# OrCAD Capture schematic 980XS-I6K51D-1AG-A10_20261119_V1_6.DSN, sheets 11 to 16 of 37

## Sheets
11 P0033_S3_MIPI: size A2
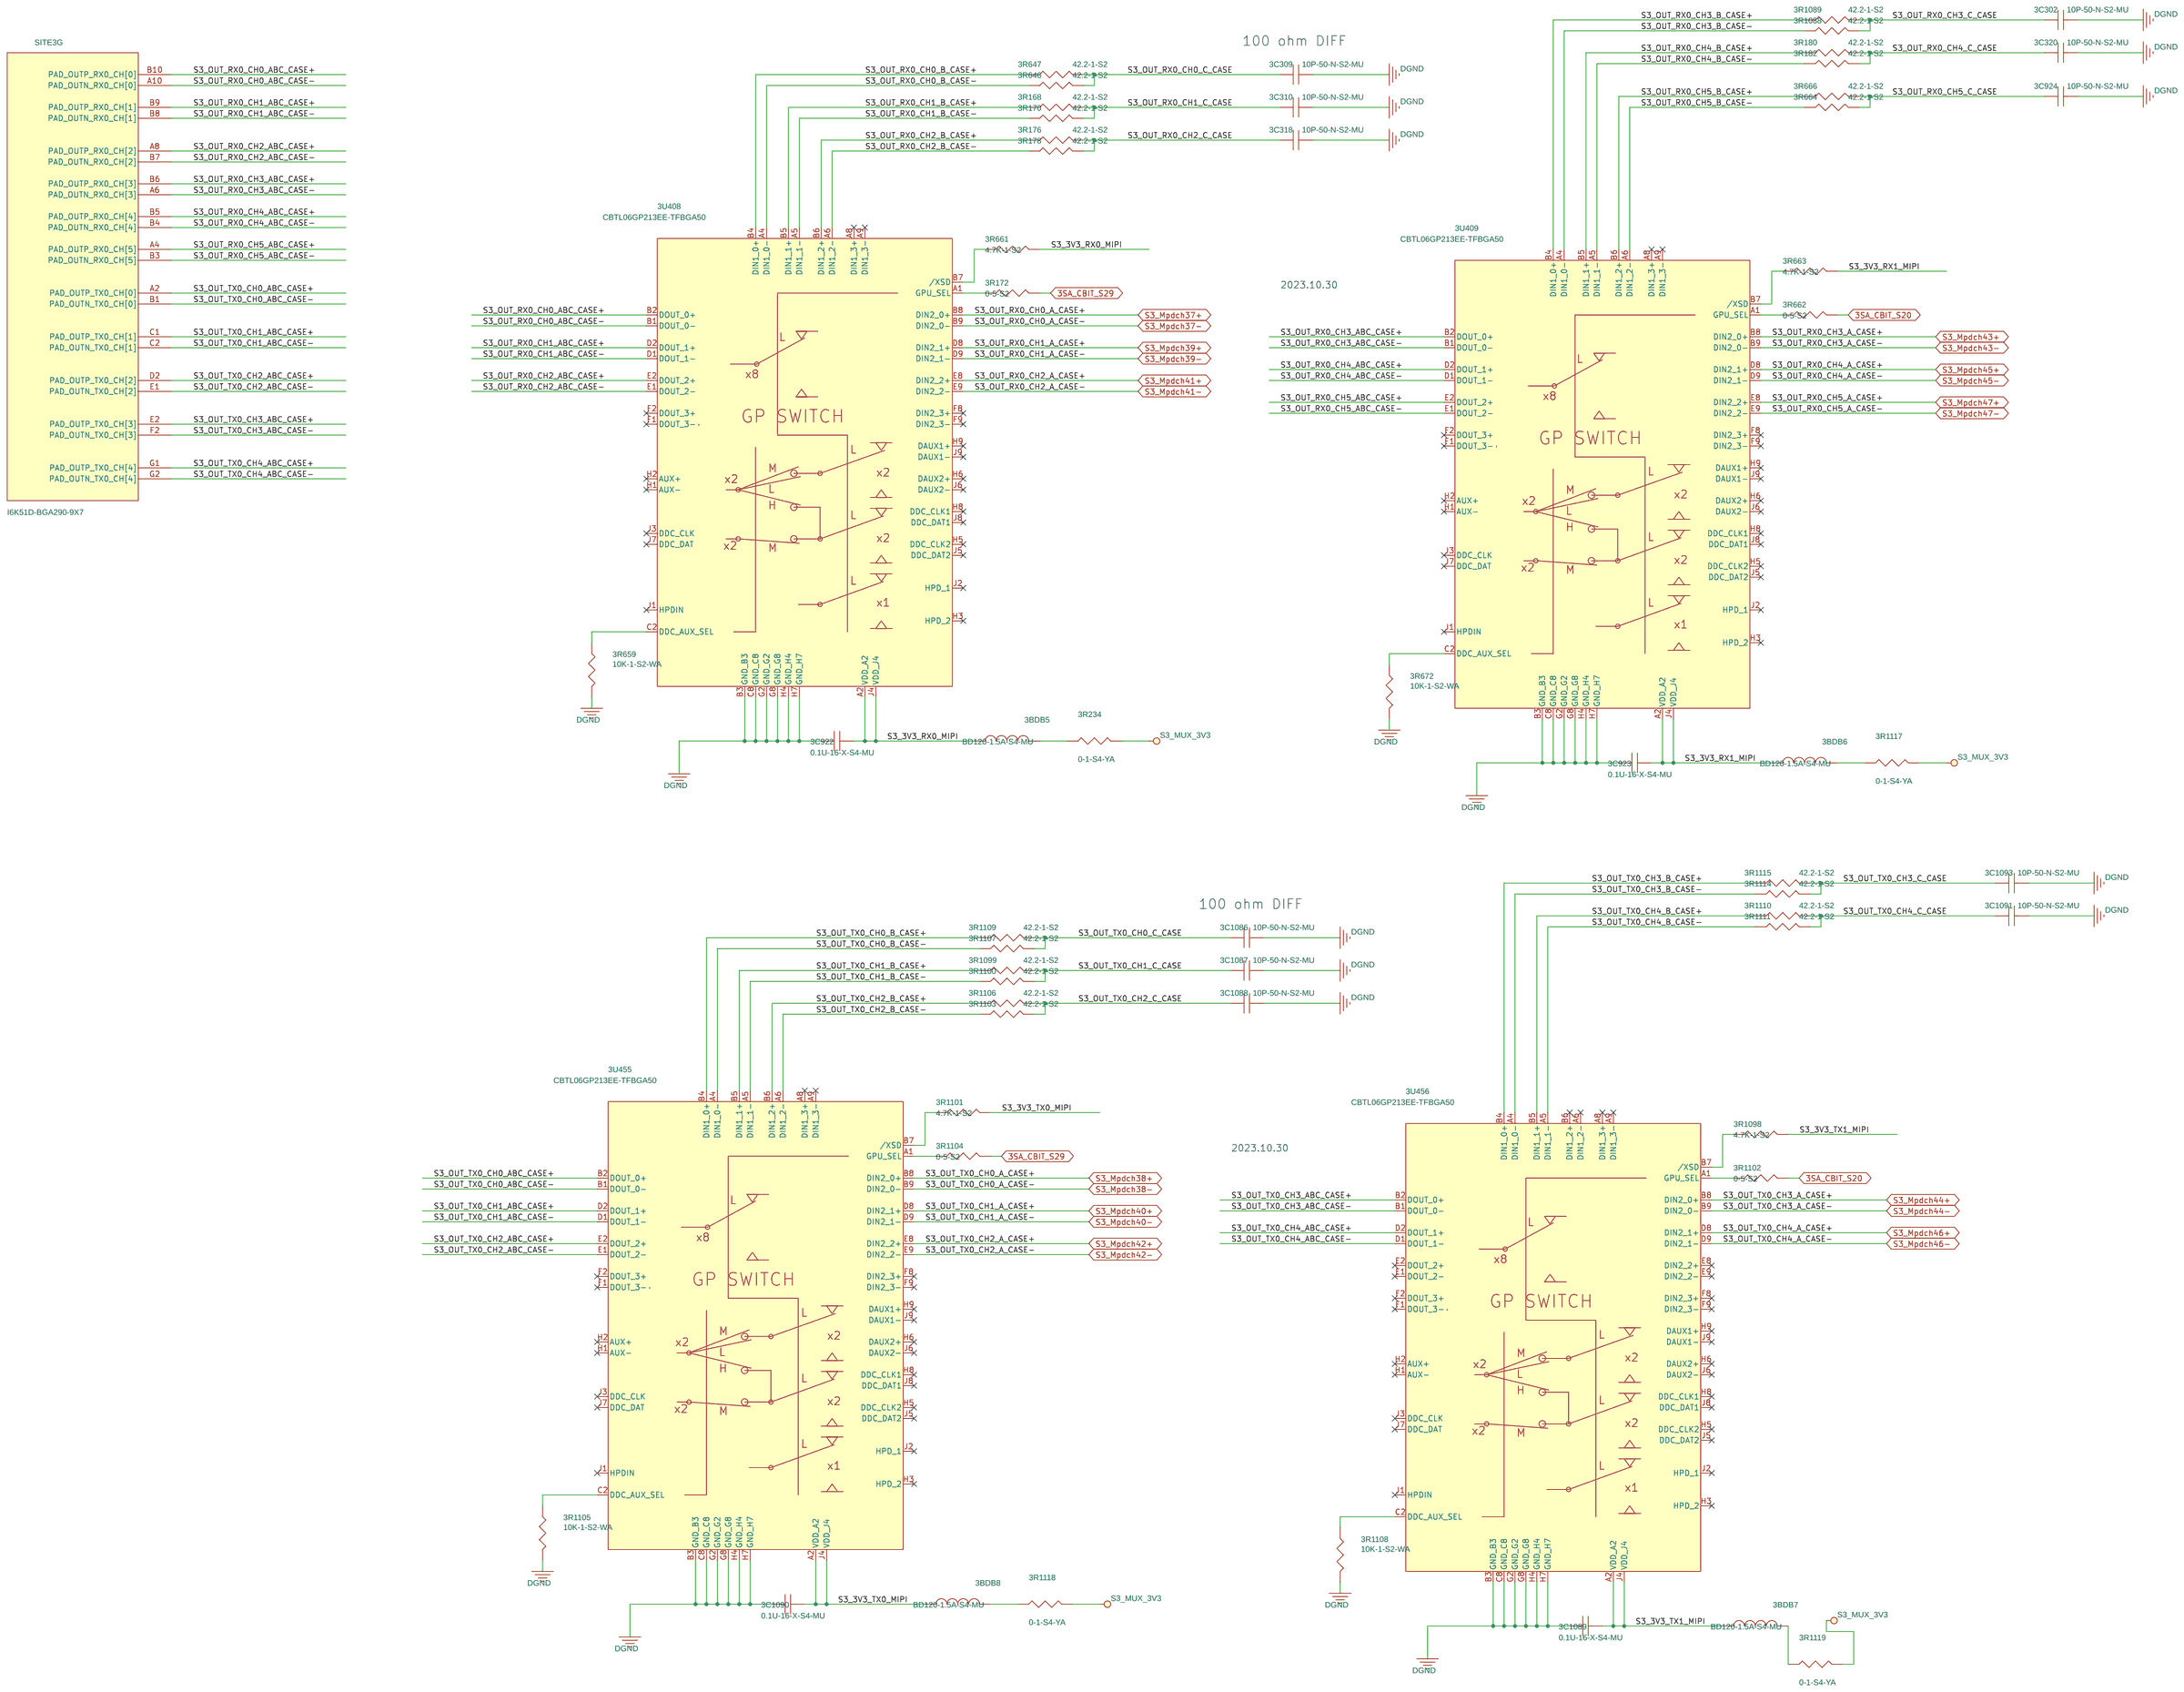
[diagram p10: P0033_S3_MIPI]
12 P0031_S3_POWER: size A2
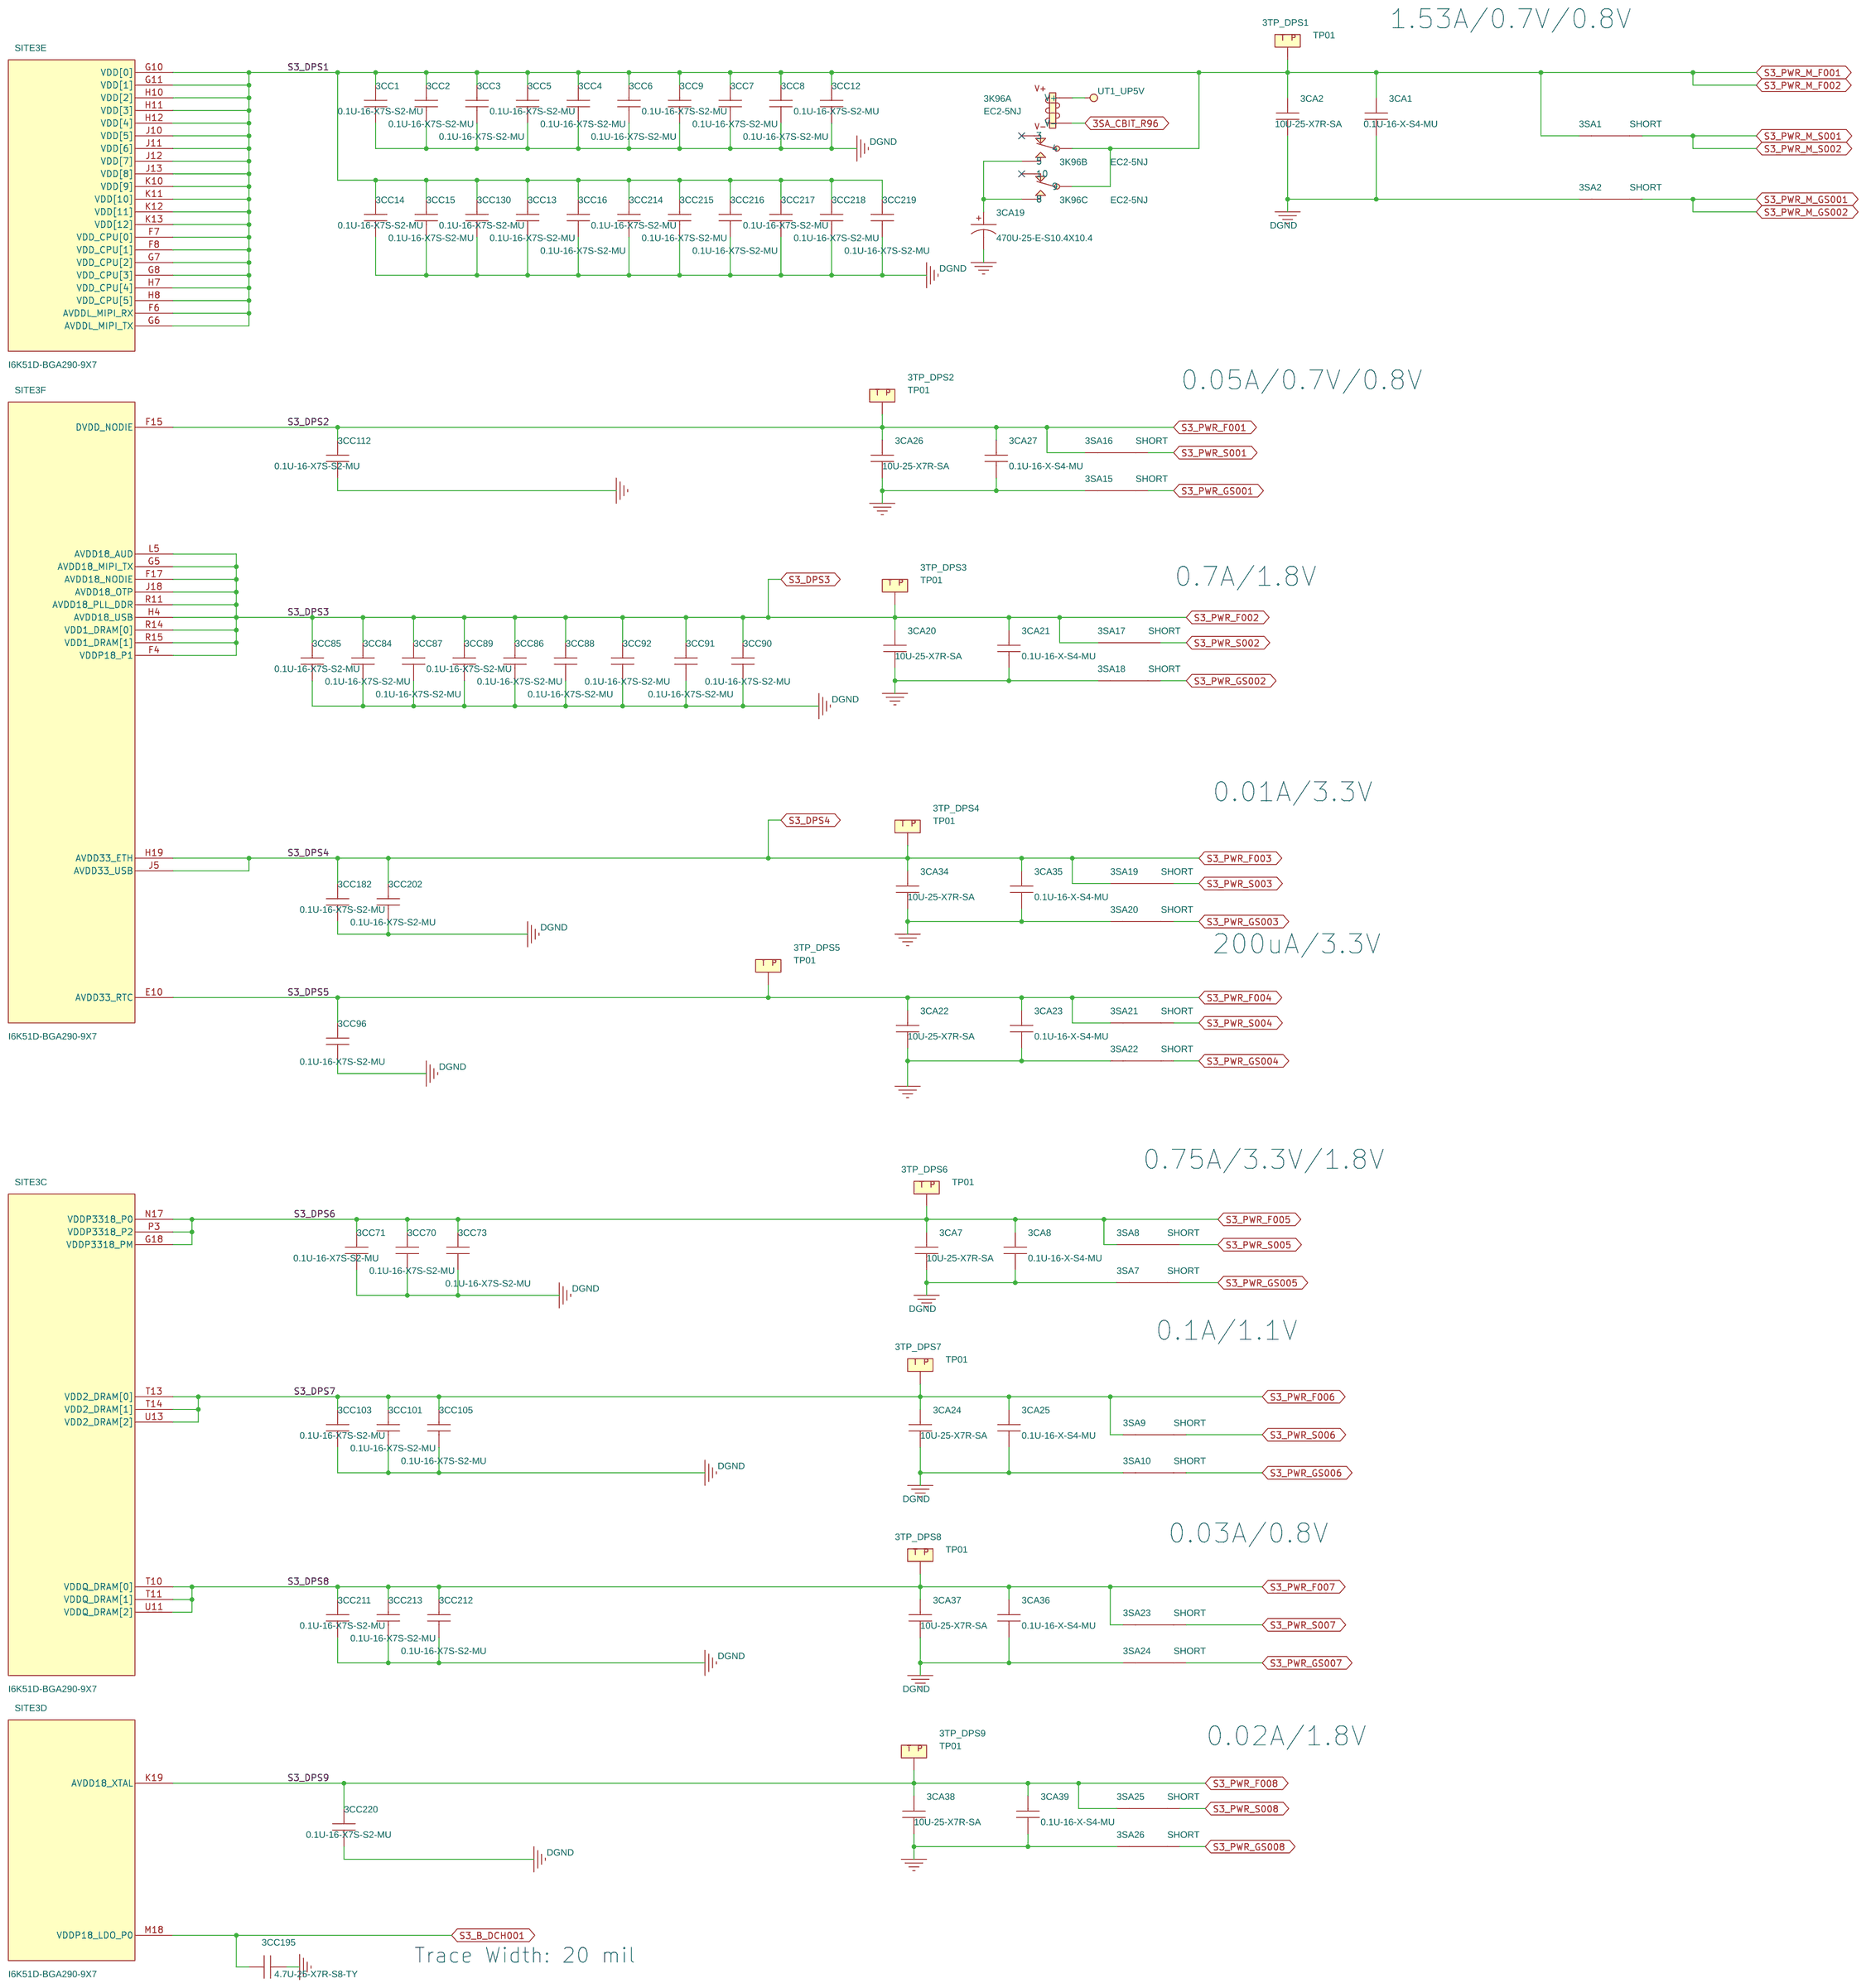
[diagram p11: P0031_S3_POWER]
13 P0023_S2_MIPI: size A2
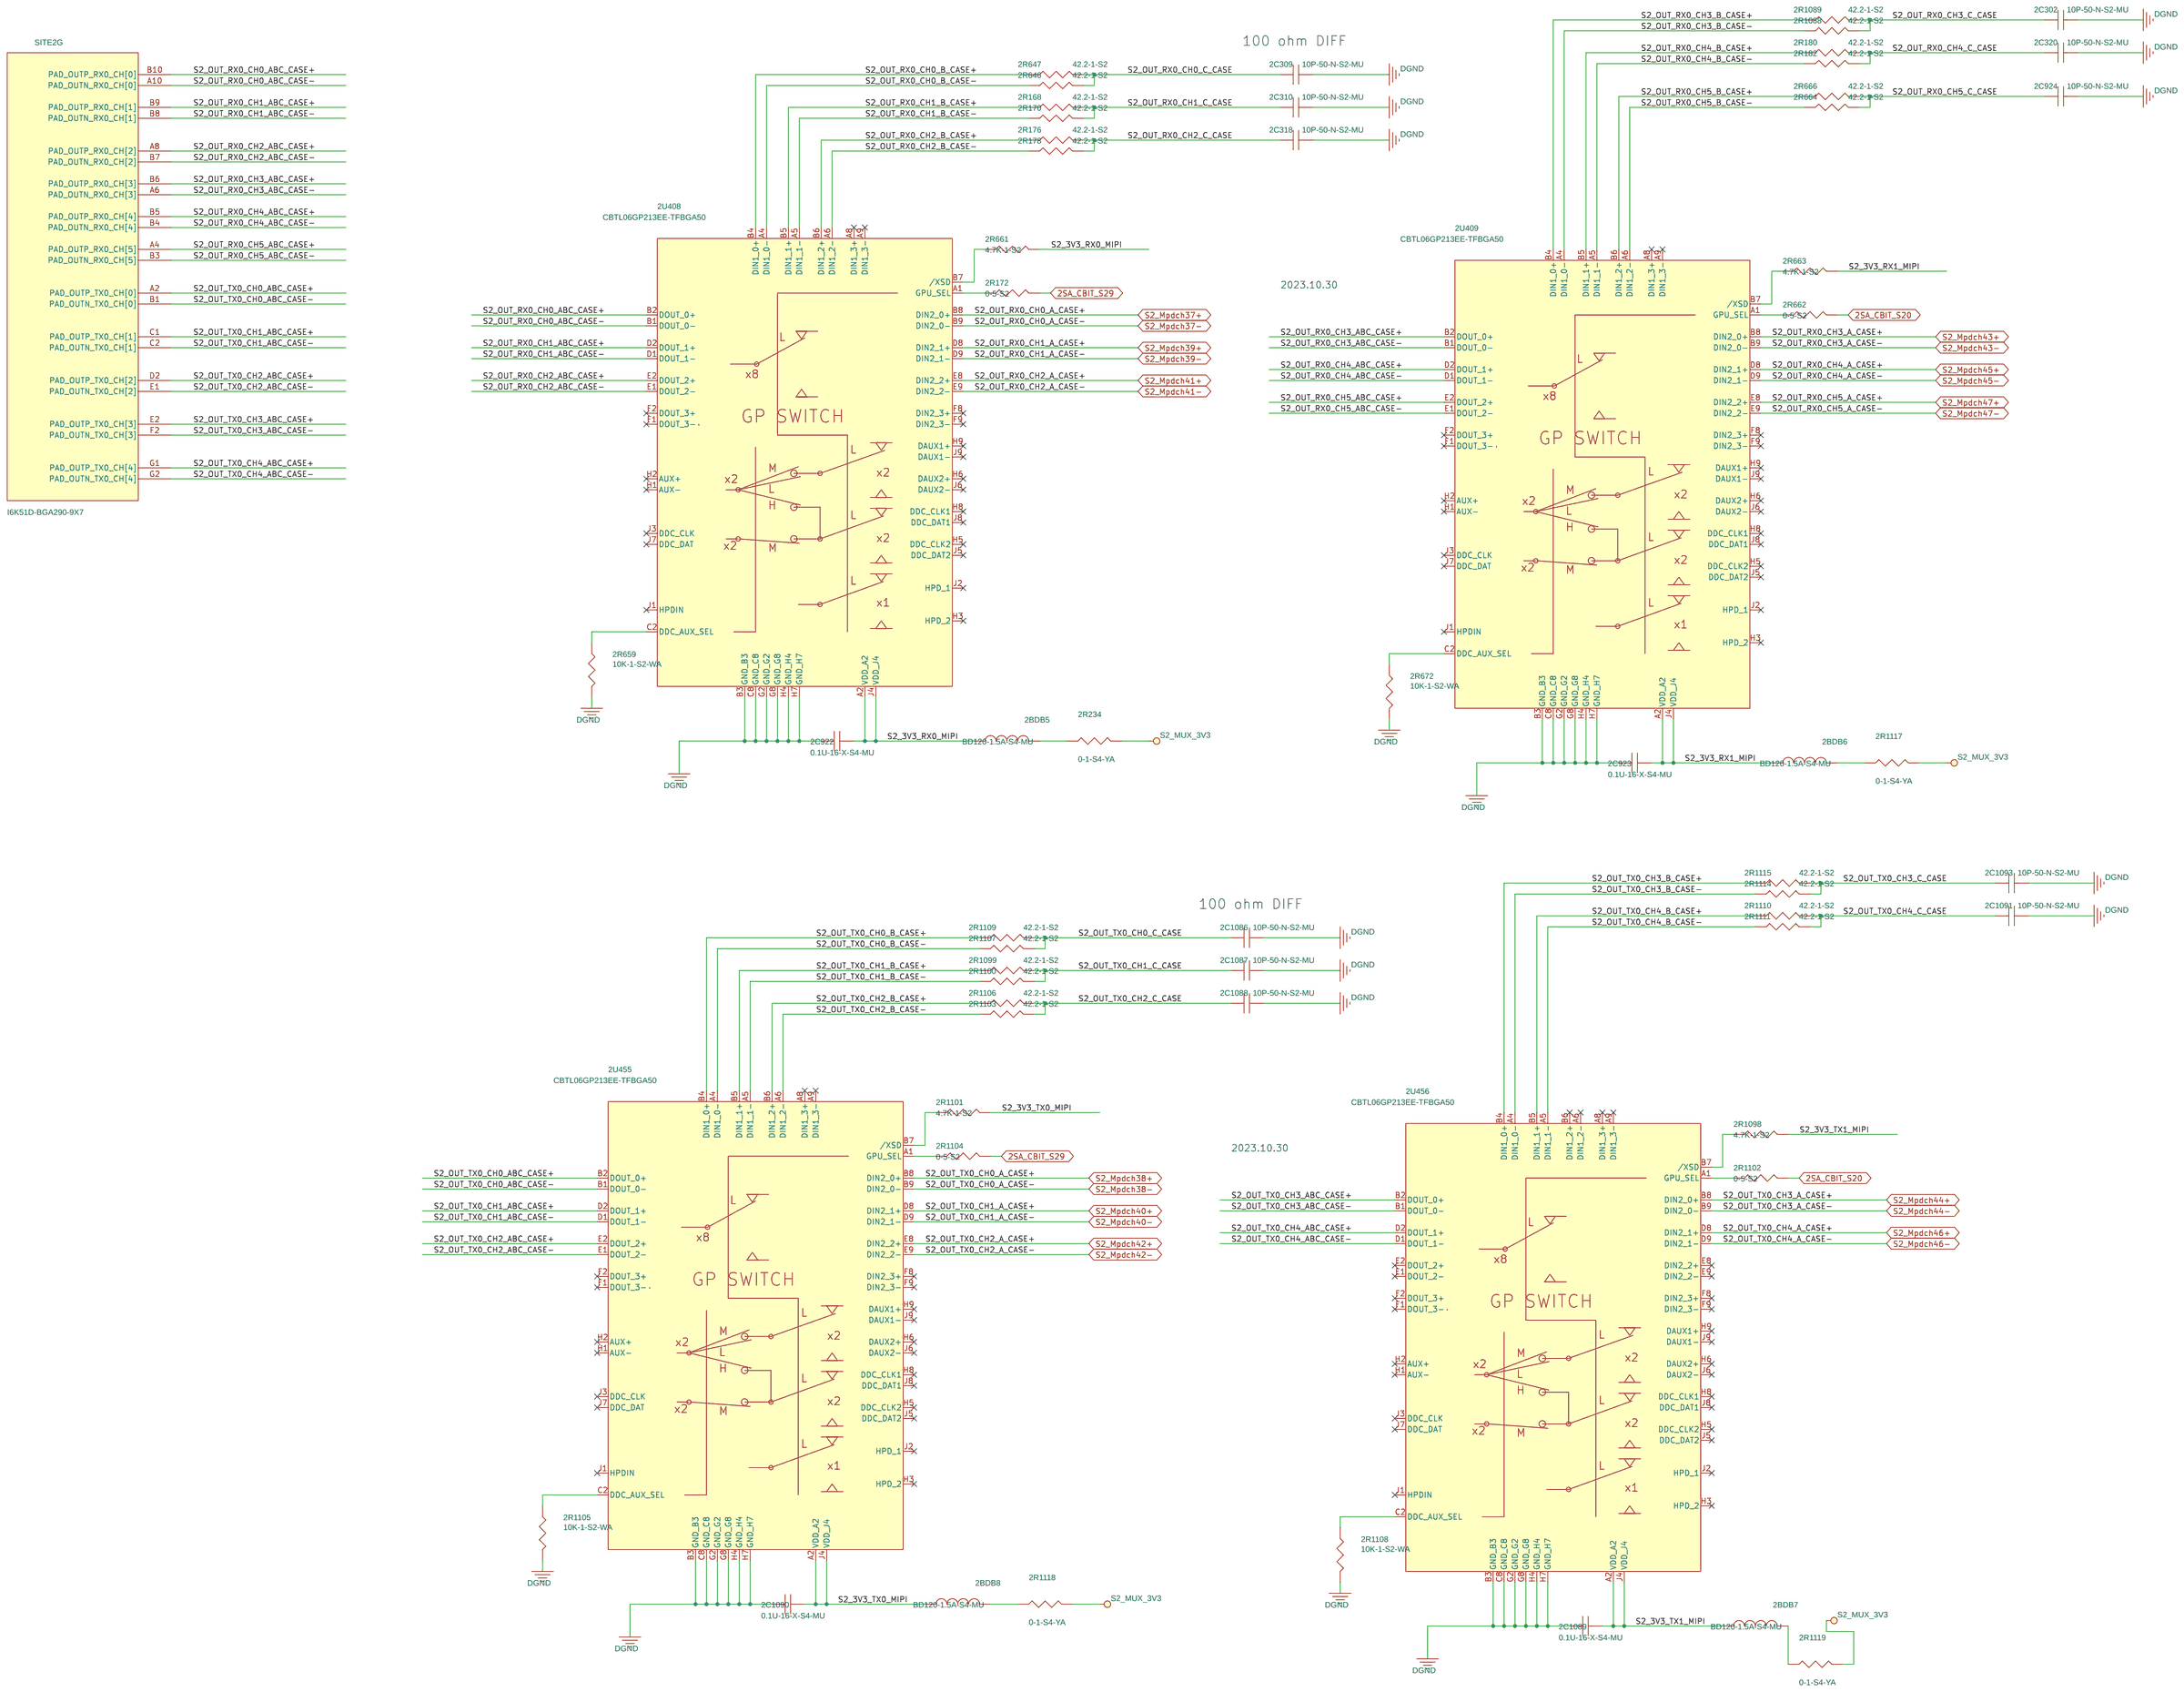
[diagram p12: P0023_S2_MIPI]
14 P0021_S2_POWER: size A2
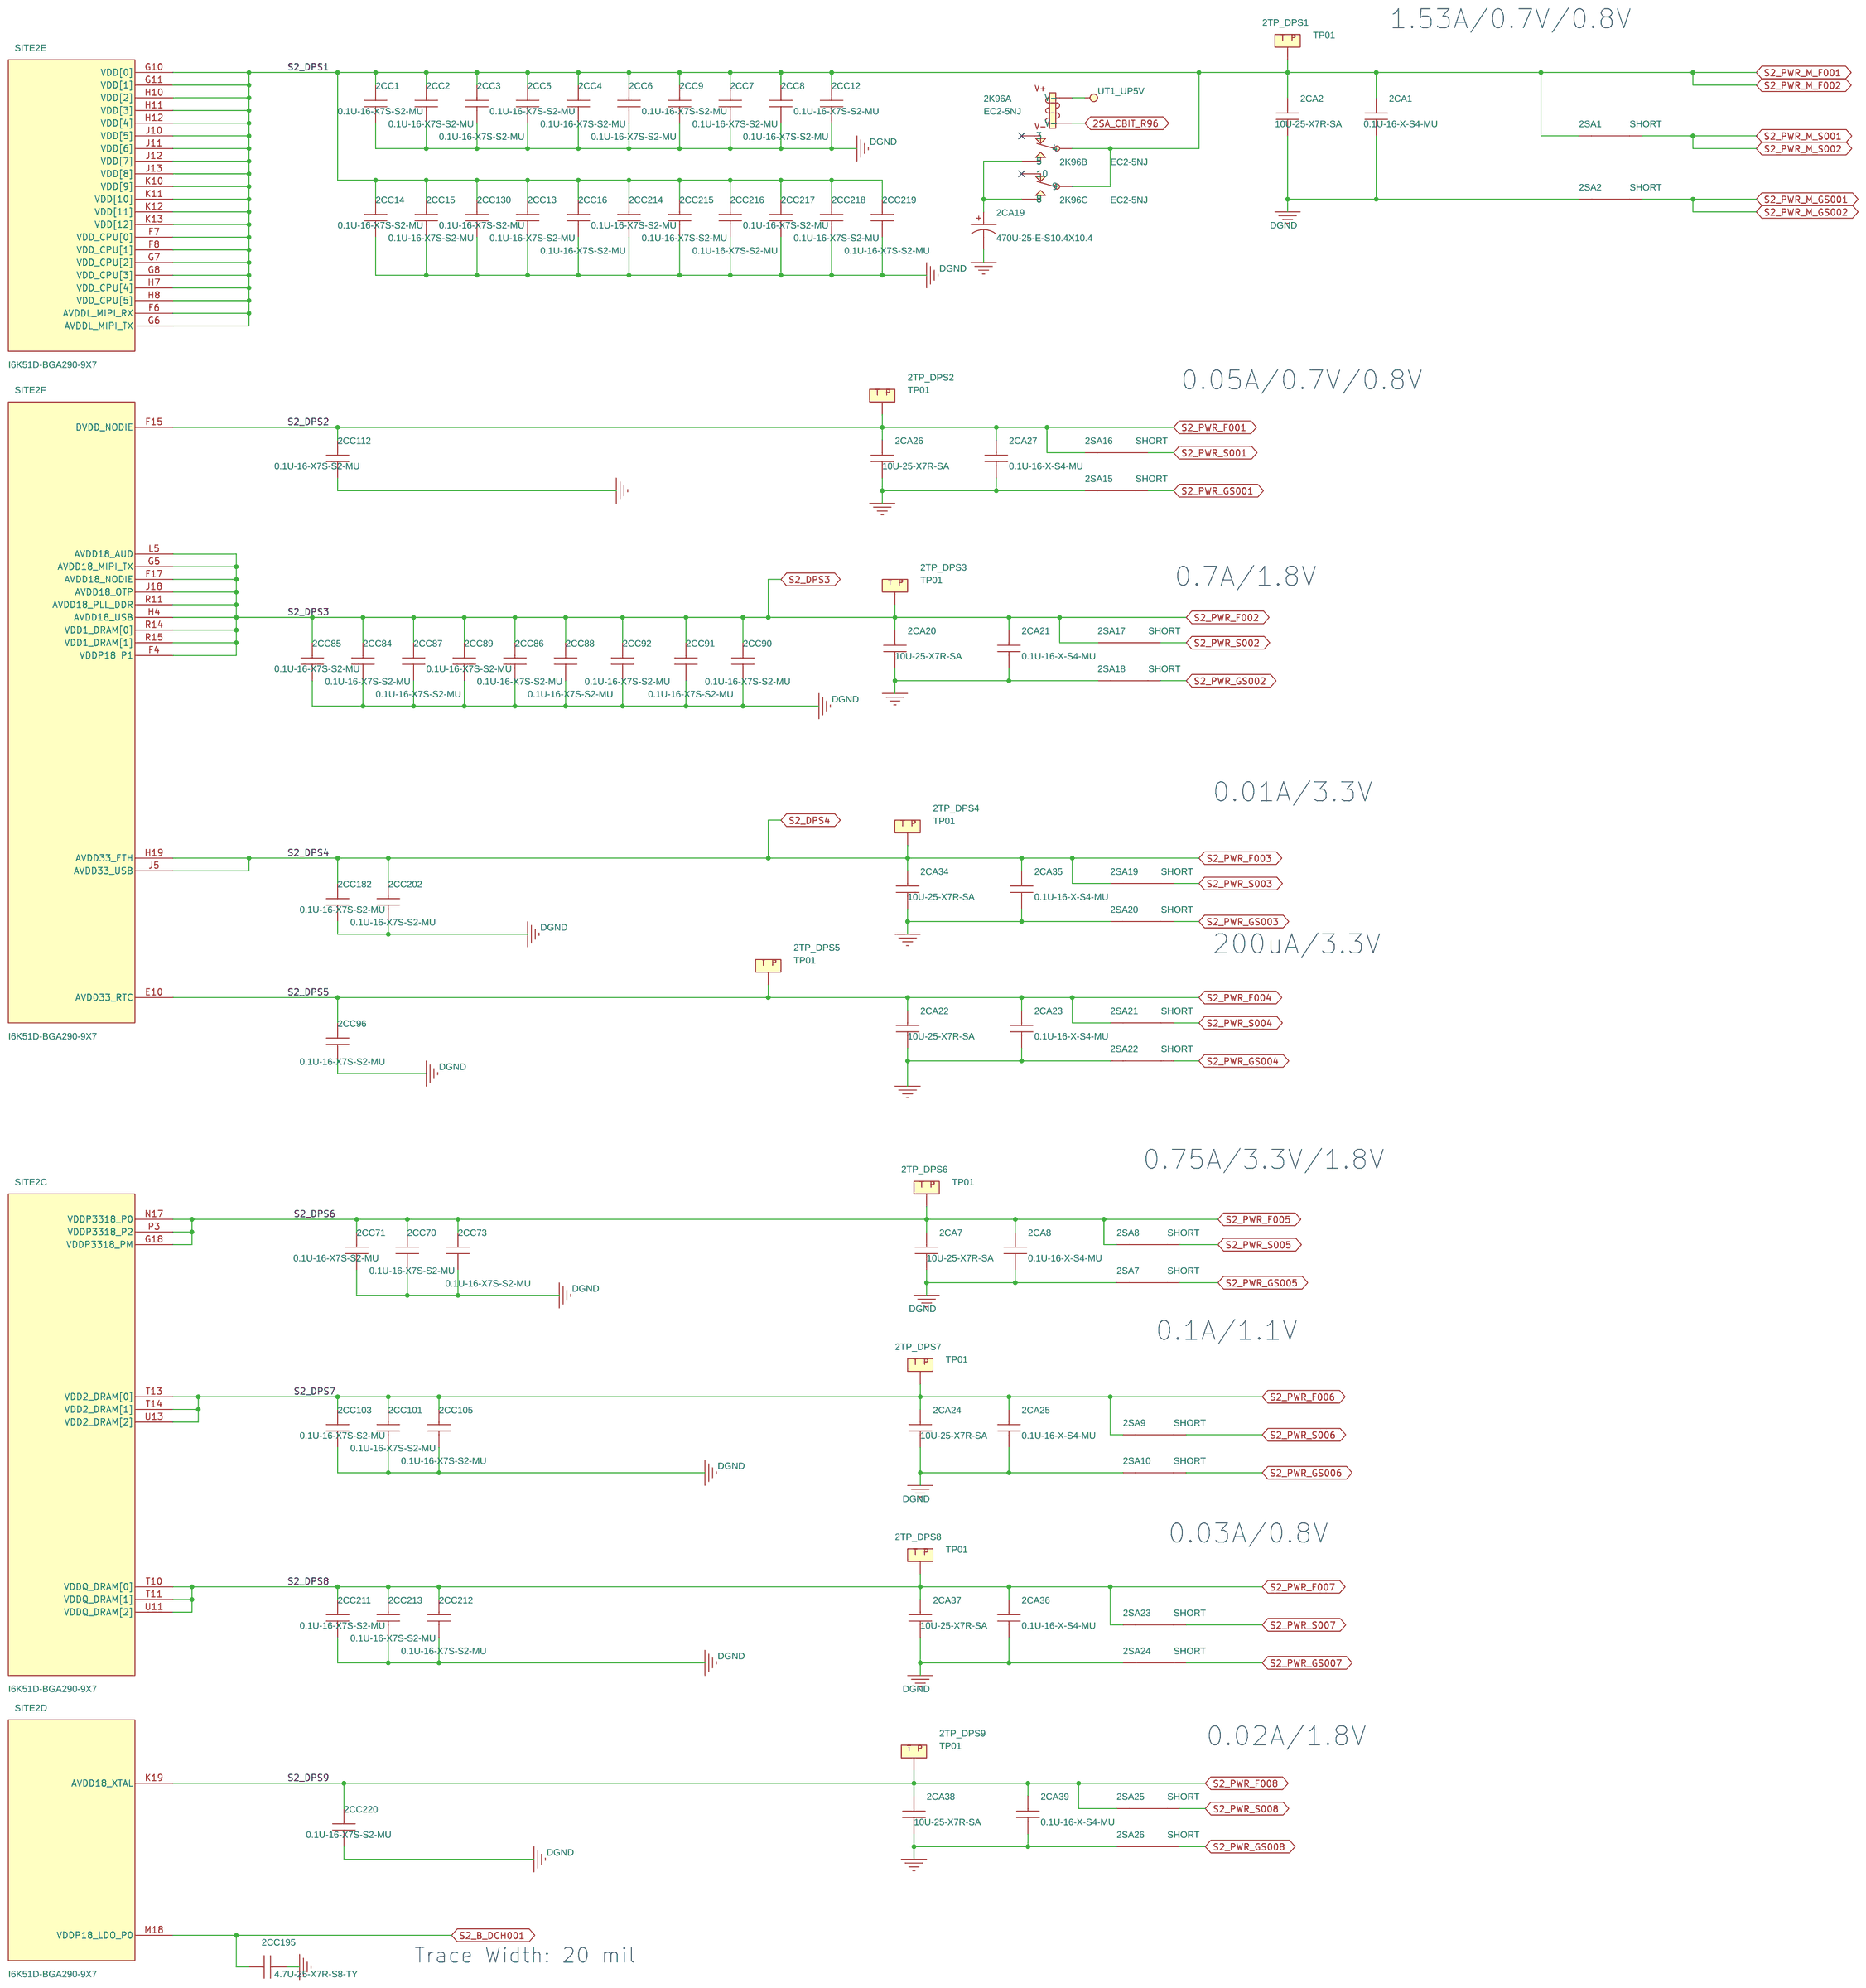
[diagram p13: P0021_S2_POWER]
15 A001-V93K_TESTConfig
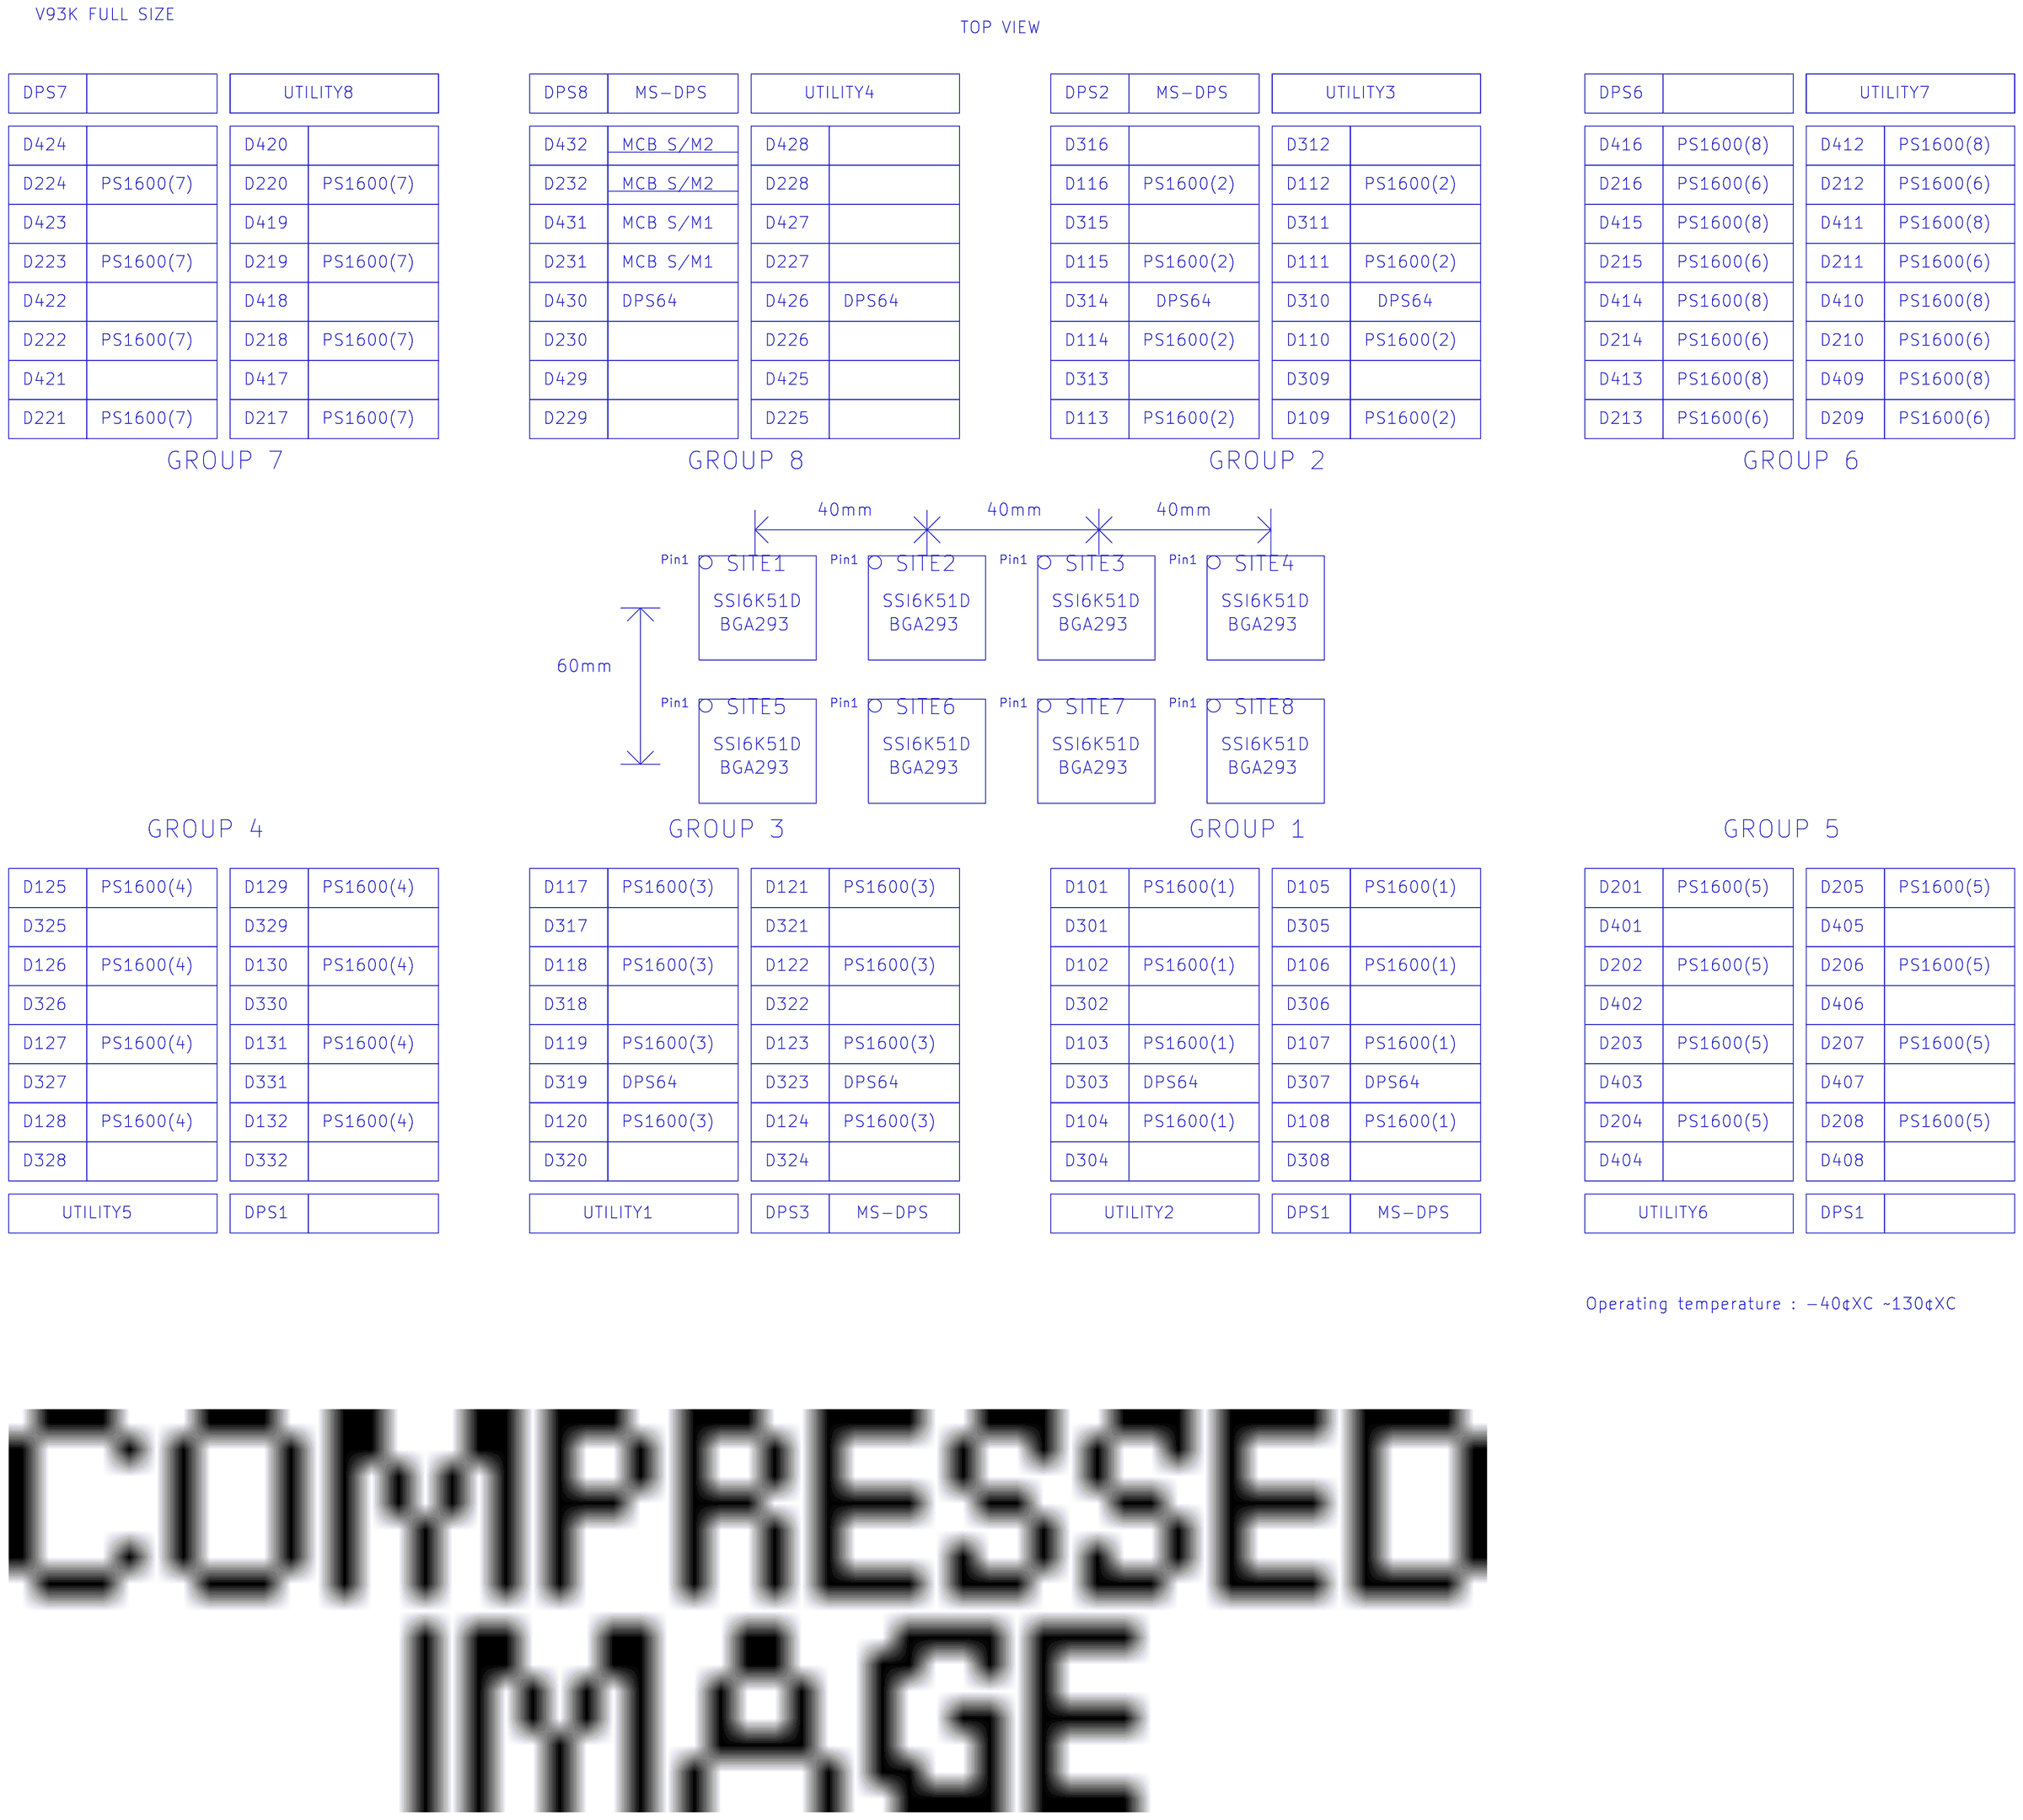
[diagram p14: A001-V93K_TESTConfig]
16 A002-History
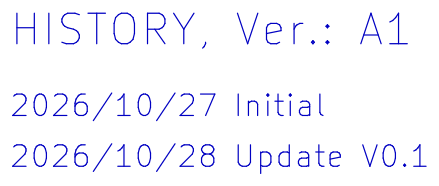
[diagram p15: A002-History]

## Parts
sheet P0021_S2_POWER
2CA1  0.1U-16-X-S4-MU  [C0402]
2CA2  10U-25-X7R-SA  [C1206]
2CA7  10U-25-X7R-SA  [C1206]
2CA8  0.1U-16-X-S4-MU  [C0402]
2CA19  470U-25-E-S10.4X10.4  [EC_10P3X10_S]
2CA20  10U-25-X7R-SA  [C1206]
2CA21  0.1U-16-X-S4-MU  [C0402]
2CA22  10U-25-X7R-SA  [C1206]
2CA23  0.1U-16-X-S4-MU  [C0402]
2CA24  10U-25-X7R-SA  [C1206]
2CA25  0.1U-16-X-S4-MU  [C0402]
2CA26  10U-25-X7R-SA  [C1206]
2CA27  0.1U-16-X-S4-MU  [C0402]
2CA34  10U-25-X7R-SA  [C1206]
2CA35  0.1U-16-X-S4-MU  [C0402]
2CA36  0.1U-16-X-S4-MU  [C0402]
2CA37  10U-25-X7R-SA  [C1206]
2CA38  10U-25-X7R-SA  [C1206]
2CA39  0.1U-16-X-S4-MU  [C0402]
2CC1  0.1U-16-X7S-S2-MU  [C0201_MINI]
2CC2  0.1U-16-X7S-S2-MU  [C0201_MINI]
2CC3  0.1U-16-X7S-S2-MU  [C0201_MINI]
2CC4  0.1U-16-X7S-S2-MU  [C0201_MINI]
2CC5  0.1U-16-X7S-S2-MU  [C0201_MINI]
2CC6  0.1U-16-X7S-S2-MU  [C0201_MINI]
2CC7  0.1U-16-X7S-S2-MU  [C0201_MINI]
2CC8  0.1U-16-X7S-S2-MU  [C0201_MINI]
2CC9  0.1U-16-X7S-S2-MU  [C0201_MINI]
2CC12  0.1U-16-X7S-S2-MU  [C0201_MINI]
2CC13  0.1U-16-X7S-S2-MU  [C0201_MINI]
2CC14  0.1U-16-X7S-S2-MU  [C0201_MINI]
2CC15  0.1U-16-X7S-S2-MU  [C0201_MINI]
2CC16  0.1U-16-X7S-S2-MU  [C0201_MINI]
2CC70  0.1U-16-X7S-S2-MU  [C0201_MINI]
2CC71  0.1U-16-X7S-S2-MU  [C0201_MINI]
2CC73  0.1U-16-X7S-S2-MU  [C0201_MINI]
2CC84  0.1U-16-X7S-S2-MU  [C0201_MINI]
2CC85  0.1U-16-X7S-S2-MU  [C0201_MINI]
2CC86  0.1U-16-X7S-S2-MU  [C0201_MINI]
2CC87  0.1U-16-X7S-S2-MU  [C0201_MINI]
2CC88  0.1U-16-X7S-S2-MU  [C0201_MINI]
2CC89  0.1U-16-X7S-S2-MU  [C0201_MINI]
2CC90  0.1U-16-X7S-S2-MU  [C0201_MINI]
2CC91  0.1U-16-X7S-S2-MU  [C0201_MINI]
2CC92  0.1U-16-X7S-S2-MU  [C0201_MINI]
2CC96  0.1U-16-X7S-S2-MU  [C0201_MINI]
2CC101  0.1U-16-X7S-S2-MU  [C0201_MINI]
2CC103  0.1U-16-X7S-S2-MU  [C0201_MINI]
2CC105  0.1U-16-X7S-S2-MU  [C0201_MINI]
2CC112  0.1U-16-X7S-S2-MU  [C0201_MINI]
2CC130  0.1U-16-X7S-S2-MU  [C0201_MINI]
2CC182  0.1U-16-X7S-S2-MU  [C0201_MINI]
2CC195  4.7U-25-X7R-S8-TY  [C0805]
2CC202  0.1U-16-X7S-S2-MU  [C0201_MINI]
2CC211  0.1U-16-X7S-S2-MU  [C0201_MINI]
2CC212  0.1U-16-X7S-S2-MU  [C0201_MINI]
2CC213  0.1U-16-X7S-S2-MU  [C0201_MINI]
2CC214  0.1U-16-X7S-S2-MU  [C0201_MINI]
2CC215  0.1U-16-X7S-S2-MU  [C0201_MINI]
2CC216  0.1U-16-X7S-S2-MU  [C0201_MINI]
2CC217  0.1U-16-X7S-S2-MU  [C0201_MINI]
2CC218  0.1U-16-X7S-S2-MU  [C0201_MINI]
2CC219  0.1U-16-X7S-S2-MU  [C0201_MINI]
2CC220  0.1U-16-X7S-S2-MU  [C0201_MINI]
2K96  EC2-5NJ  [RL_NECEC2_10P_5V]  (sections A,B,C)
2SA1  SHORT  [DEFAULT_SHORT_SMALL]
2SA2  SHORT  [DEFAULT_SHORT_SMALL]
2SA7  SHORT  [DEFAULT_SHORT_SMALL]
2SA8  SHORT  [DEFAULT_SHORT_SMALL]
2SA9  SHORT  [DEFAULT_SHORT_SMALL]
2SA10  SHORT  [DEFAULT_SHORT_SMALL]
2SA15  SHORT  [DEFAULT_SHORT_SMALL]
2SA16  SHORT  [DEFAULT_SHORT_SMALL]
2SA17  SHORT  [DEFAULT_SHORT_SMALL]
2SA18  SHORT  [DEFAULT_SHORT_SMALL]
2SA19  SHORT  [DEFAULT_SHORT_SMALL]
2SA20  SHORT  [DEFAULT_SHORT_SMALL]
2SA21  SHORT  [DEFAULT_SHORT_SMALL]
2SA22  SHORT  [DEFAULT_SHORT_SMALL]
2SA23  SHORT  [DEFAULT_SHORT_SMALL]
2SA24  SHORT  [DEFAULT_SHORT_SMALL]
2SA25  SHORT  [DEFAULT_SHORT_SMALL]
2SA26  SHORT  [DEFAULT_SHORT_SMALL]
2TP_DPS1  TP01  [TP_040_T]
2TP_DPS2  TP01  [TP_040_T]
2TP_DPS3  TP01  [TP_040_T]
2TP_DPS4  TP01  [TP_040_T]
2TP_DPS5  TP01  [TP_040_T]
2TP_DPS6  TP01  [TP_040_T]
2TP_DPS7  TP01  [TP_040_T]
2TP_DPS8  TP01  [TP_040_T]
2TP_DPS9  TP01  [TP_040_T]
SITE2  I6K51D-BGA290-9X7  [SK_TFBGA7X9_290P_0P4MM_JG]  (sections A,B,C,D,E,F,G,H,I,J,K,L,M,N,O)
sheet P0023_S2_MIPI
2BDB5  BD120-1.5A-S4-MU  [FB0402]
2BDB6  BD120-1.5A-S4-MU  [FB0402]
2BDB7  BD120-1.5A-S4-MU  [FB0402]
2BDB8  BD120-1.5A-S4-MU  [FB0402]
2C302  10P-50-N-S2-MU  [C0201]
2C309  10P-50-N-S2-MU  [C0201]
2C310  10P-50-N-S2-MU  [C0201]
2C318  10P-50-N-S2-MU  [C0201]
2C320  10P-50-N-S2-MU  [C0201]
2C922  0.1U-16-X-S4-MU  [C0402]
2C923  0.1U-16-X-S4-MU  [C0402]
2C924  10P-50-N-S2-MU  [C0201]
2C1086  10P-50-N-S2-MU  [C0201]
2C1087  10P-50-N-S2-MU  [C0201]
2C1088  10P-50-N-S2-MU  [C0201]
2C1089  0.1U-16-X-S4-MU  [C0402]
2C1090  0.1U-16-X-S4-MU  [C0402]
2C1091  10P-50-N-S2-MU  [C0201]
2C1093  10P-50-N-S2-MU  [C0201]
2R168  42.2-1-S2  [R0201]
2R170  42.2-1-S2  [R0201]
2R172  0-5-S2  [R0201]
2R176  42.2-1-S2  [R0201]
2R178  42.2-1-S2  [R0201]
2R180  42.2-1-S2  [R0201]
2R182  42.2-1-S2  [R0201]
2R234  0-1-S4-YA  [R0402]
2R646  42.2-1-S2  [R0201]
2R647  42.2-1-S2  [R0201]
2R659  10K-1-S2-WA  [R0201]
2R661  4.7K-1-S2  [R0201]
2R662  0-5-S2  [R0201]
2R663  4.7K-1-S2  [R0201]
2R664  42.2-1-S2  [R0201]
2R666  42.2-1-S2  [R0201]
2R672  10K-1-S2-WA  [R0201]
2R1088  42.2-1-S2  [R0201]
2R1089  42.2-1-S2  [R0201]
2R1098  4.7K-1-S2  [R0201]
2R1099  42.2-1-S2  [R0201]
2R1100  42.2-1-S2  [R0201]
2R1101  4.7K-1-S2  [R0201]
2R1102  0-5-S2  [R0201]
2R1103  42.2-1-S2  [R0201]
2R1104  0-5-S2  [R0201]
2R1105  10K-1-S2-WA  [R0201]
2R1106  42.2-1-S2  [R0201]
2R1107  42.2-1-S2  [R0201]
2R1108  10K-1-S2-WA  [R0201]
2R1109  42.2-1-S2  [R0201]
2R1110  42.2-1-S2  [R0201]
2R1111  42.2-1-S2  [R0201]
2R1114  42.2-1-S2  [R0201]
2R1115  42.2-1-S2  [R0201]
2R1117  0-1-S4-YA  [R0402]
2R1118  0-1-S4-YA  [R0402]
2R1119  0-1-S4-YA  [R0402]
2U408  CBTL06GP213EE-TFBGA50  [TFBGA9X9_50P_0P5MM]
2U409  CBTL06GP213EE-TFBGA50  [TFBGA9X9_50P_0P5MM]
2U455  CBTL06GP213EE-TFBGA50  [TFBGA9X9_50P_0P5MM]
2U456  CBTL06GP213EE-TFBGA50  [TFBGA9X9_50P_0P5MM]
sheet P0031_S3_POWER
3CA1  0.1U-16-X-S4-MU  [C0402]
3CA2  10U-25-X7R-SA  [C1206]
3CA7  10U-25-X7R-SA  [C1206]
3CA8  0.1U-16-X-S4-MU  [C0402]
3CA19  470U-25-E-S10.4X10.4  [EC_10P3X10_S]
3CA20  10U-25-X7R-SA  [C1206]
3CA21  0.1U-16-X-S4-MU  [C0402]
3CA22  10U-25-X7R-SA  [C1206]
3CA23  0.1U-16-X-S4-MU  [C0402]
3CA24  10U-25-X7R-SA  [C1206]
3CA25  0.1U-16-X-S4-MU  [C0402]
3CA26  10U-25-X7R-SA  [C1206]
3CA27  0.1U-16-X-S4-MU  [C0402]
3CA34  10U-25-X7R-SA  [C1206]
3CA35  0.1U-16-X-S4-MU  [C0402]
3CA36  0.1U-16-X-S4-MU  [C0402]
3CA37  10U-25-X7R-SA  [C1206]
3CA38  10U-25-X7R-SA  [C1206]
3CA39  0.1U-16-X-S4-MU  [C0402]
3CC1  0.1U-16-X7S-S2-MU  [C0201_MINI]
3CC2  0.1U-16-X7S-S2-MU  [C0201_MINI]
3CC3  0.1U-16-X7S-S2-MU  [C0201_MINI]
3CC4  0.1U-16-X7S-S2-MU  [C0201_MINI]
3CC5  0.1U-16-X7S-S2-MU  [C0201_MINI]
3CC6  0.1U-16-X7S-S2-MU  [C0201_MINI]
3CC7  0.1U-16-X7S-S2-MU  [C0201_MINI]
3CC8  0.1U-16-X7S-S2-MU  [C0201_MINI]
3CC9  0.1U-16-X7S-S2-MU  [C0201_MINI]
3CC12  0.1U-16-X7S-S2-MU  [C0201_MINI]
3CC13  0.1U-16-X7S-S2-MU  [C0201_MINI]
3CC14  0.1U-16-X7S-S2-MU  [C0201_MINI]
3CC15  0.1U-16-X7S-S2-MU  [C0201_MINI]
3CC16  0.1U-16-X7S-S2-MU  [C0201_MINI]
3CC70  0.1U-16-X7S-S2-MU  [C0201_MINI]
3CC71  0.1U-16-X7S-S2-MU  [C0201_MINI]
3CC73  0.1U-16-X7S-S2-MU  [C0201_MINI]
3CC84  0.1U-16-X7S-S2-MU  [C0201_MINI]
3CC85  0.1U-16-X7S-S2-MU  [C0201_MINI]
3CC86  0.1U-16-X7S-S2-MU  [C0201_MINI]
3CC87  0.1U-16-X7S-S2-MU  [C0201_MINI]
3CC88  0.1U-16-X7S-S2-MU  [C0201_MINI]
3CC89  0.1U-16-X7S-S2-MU  [C0201_MINI]
3CC90  0.1U-16-X7S-S2-MU  [C0201_MINI]
3CC91  0.1U-16-X7S-S2-MU  [C0201_MINI]
3CC92  0.1U-16-X7S-S2-MU  [C0201_MINI]
3CC96  0.1U-16-X7S-S2-MU  [C0201_MINI]
3CC101  0.1U-16-X7S-S2-MU  [C0201_MINI]
3CC103  0.1U-16-X7S-S2-MU  [C0201_MINI]
3CC105  0.1U-16-X7S-S2-MU  [C0201_MINI]
3CC112  0.1U-16-X7S-S2-MU  [C0201_MINI]
3CC130  0.1U-16-X7S-S2-MU  [C0201_MINI]
3CC182  0.1U-16-X7S-S2-MU  [C0201_MINI]
3CC195  4.7U-25-X7R-S8-TY  [C0805]
3CC202  0.1U-16-X7S-S2-MU  [C0201_MINI]
3CC211  0.1U-16-X7S-S2-MU  [C0201_MINI]
3CC212  0.1U-16-X7S-S2-MU  [C0201_MINI]
3CC213  0.1U-16-X7S-S2-MU  [C0201_MINI]
3CC214  0.1U-16-X7S-S2-MU  [C0201_MINI]
3CC215  0.1U-16-X7S-S2-MU  [C0201_MINI]
3CC216  0.1U-16-X7S-S2-MU  [C0201_MINI]
3CC217  0.1U-16-X7S-S2-MU  [C0201_MINI]
3CC218  0.1U-16-X7S-S2-MU  [C0201_MINI]
3CC219  0.1U-16-X7S-S2-MU  [C0201_MINI]
3CC220  0.1U-16-X7S-S2-MU  [C0201_MINI]
3K96  EC2-5NJ  [RL_NECEC2_10P_5V]  (sections A,B,C)
3SA1  SHORT  [DEFAULT_SHORT_SMALL]
3SA2  SHORT  [DEFAULT_SHORT_SMALL]
3SA7  SHORT  [DEFAULT_SHORT_SMALL]
3SA8  SHORT  [DEFAULT_SHORT_SMALL]
3SA9  SHORT  [DEFAULT_SHORT_SMALL]
3SA10  SHORT  [DEFAULT_SHORT_SMALL]
3SA15  SHORT  [DEFAULT_SHORT_SMALL]
3SA16  SHORT  [DEFAULT_SHORT_SMALL]
3SA17  SHORT  [DEFAULT_SHORT_SMALL]
3SA18  SHORT  [DEFAULT_SHORT_SMALL]
3SA19  SHORT  [DEFAULT_SHORT_SMALL]
3SA20  SHORT  [DEFAULT_SHORT_SMALL]
3SA21  SHORT  [DEFAULT_SHORT_SMALL]
3SA22  SHORT  [DEFAULT_SHORT_SMALL]
3SA23  SHORT  [DEFAULT_SHORT_SMALL]
3SA24  SHORT  [DEFAULT_SHORT_SMALL]
3SA25  SHORT  [DEFAULT_SHORT_SMALL]
3SA26  SHORT  [DEFAULT_SHORT_SMALL]
3TP_DPS1  TP01  [TP_040_T]
3TP_DPS2  TP01  [TP_040_T]
3TP_DPS3  TP01  [TP_040_T]
3TP_DPS4  TP01  [TP_040_T]
3TP_DPS5  TP01  [TP_040_T]
3TP_DPS6  TP01  [TP_040_T]
3TP_DPS7  TP01  [TP_040_T]
3TP_DPS8  TP01  [TP_040_T]
3TP_DPS9  TP01  [TP_040_T]
sheet P0032_S3_USB/AUD/FLASH/XTAL
SITE3  I6K51D-BGA290-9X7  [SK_TFBGA7X9_290P_0P4MM_JG]  (sections A,B,C,D,E,F,G,H,I,J,K,L,M,N,O)
sheet P0033_S3_MIPI
3BDB5  BD120-1.5A-S4-MU  [FB0402]
3BDB6  BD120-1.5A-S4-MU  [FB0402]
3BDB7  BD120-1.5A-S4-MU  [FB0402]
3BDB8  BD120-1.5A-S4-MU  [FB0402]
3C302  10P-50-N-S2-MU  [C0201]
3C309  10P-50-N-S2-MU  [C0201]
3C310  10P-50-N-S2-MU  [C0201]
3C318  10P-50-N-S2-MU  [C0201]
3C320  10P-50-N-S2-MU  [C0201]
3C922  0.1U-16-X-S4-MU  [C0402]
3C923  0.1U-16-X-S4-MU  [C0402]
3C924  10P-50-N-S2-MU  [C0201]
3C1086  10P-50-N-S2-MU  [C0201]
3C1087  10P-50-N-S2-MU  [C0201]
3C1088  10P-50-N-S2-MU  [C0201]
3C1089  0.1U-16-X-S4-MU  [C0402]
3C1090  0.1U-16-X-S4-MU  [C0402]
3C1091  10P-50-N-S2-MU  [C0201]
3C1093  10P-50-N-S2-MU  [C0201]
3R168  42.2-1-S2  [R0201]
3R170  42.2-1-S2  [R0201]
3R172  0-5-S2  [R0201]
3R176  42.2-1-S2  [R0201]
3R178  42.2-1-S2  [R0201]
3R180  42.2-1-S2  [R0201]
3R182  42.2-1-S2  [R0201]
3R234  0-1-S4-YA  [R0402]
3R646  42.2-1-S2  [R0201]
3R647  42.2-1-S2  [R0201]
3R659  10K-1-S2-WA  [R0201]
3R661  4.7K-1-S2  [R0201]
3R662  0-5-S2  [R0201]
3R663  4.7K-1-S2  [R0201]
3R664  42.2-1-S2  [R0201]
3R666  42.2-1-S2  [R0201]
3R672  10K-1-S2-WA  [R0201]
3R1088  42.2-1-S2  [R0201]
3R1089  42.2-1-S2  [R0201]
3R1098  4.7K-1-S2  [R0201]
3R1099  42.2-1-S2  [R0201]
3R1100  42.2-1-S2  [R0201]
3R1101  4.7K-1-S2  [R0201]
3R1102  0-5-S2  [R0201]
3R1103  42.2-1-S2  [R0201]
3R1104  0-5-S2  [R0201]
3R1105  10K-1-S2-WA  [R0201]
3R1106  42.2-1-S2  [R0201]
3R1107  42.2-1-S2  [R0201]
3R1108  10K-1-S2-WA  [R0201]
3R1109  42.2-1-S2  [R0201]
3R1110  42.2-1-S2  [R0201]
3R1111  42.2-1-S2  [R0201]
3R1114  42.2-1-S2  [R0201]
3R1115  42.2-1-S2  [R0201]
3R1117  0-1-S4-YA  [R0402]
3R1118  0-1-S4-YA  [R0402]
3R1119  0-1-S4-YA  [R0402]
3U408  CBTL06GP213EE-TFBGA50  [TFBGA9X9_50P_0P5MM]
3U409  CBTL06GP213EE-TFBGA50  [TFBGA9X9_50P_0P5MM]
3U455  CBTL06GP213EE-TFBGA50  [TFBGA9X9_50P_0P5MM]
3U456  CBTL06GP213EE-TFBGA50  [TFBGA9X9_50P_0P5MM]

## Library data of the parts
2CA1 3CA1 = 0.1U-16-X-S4-MU: KAIROSNAME: CA1
2CA2 3CA2 = 10U-25-X7R-SA: KAIROSNAME: CA2
2CA7 3CA7 = 10U-25-X7R-SA: KAIROSNAME: CA7
2CA8 3CA8 = 0.1U-16-X-S4-MU: KAIROSNAME: CA8
2CA19 3CA19 = 470U-25-E-S10.4X10.4: KAIROSNAME: CA19
2CA20 2CA34 2CA38 3CA20 3CA34 3CA38 = 10U-25-X7R-SA: KAIROSNAME: CA20
2CA21 2CA35 2CA39 3CA21 3CA35 3CA39 = 0.1U-16-X-S4-MU: KAIROSNAME: CA21
2CA22 3CA22 = 10U-25-X7R-SA: KAIROSNAME: CA22
2CA23 3CA23 = 0.1U-16-X-S4-MU: KAIROSNAME: CA23
2CA24 2CA37 3CA24 3CA37 = 10U-25-X7R-SA: KAIROSNAME: CA24
2CA25 2CA36 3CA25 3CA36 = 0.1U-16-X-S4-MU: KAIROSNAME: CA25
2CA26 3CA26 = 10U-25-X7R-SA: KAIROSNAME: CA26
2CA27 3CA27 = 0.1U-16-X-S4-MU: KAIROSNAME: CA27
2CC1 2CC14 2CC16 2CC130 2CC214-2CC219 3CC1 3CC14 3CC16 3CC130 3CC214-3CC219 = 0.1U-16-X7S-S2-MU: KAIROSNAME: CC1
2CC2 2CC13 2CC15 3CC2 3CC13 3CC15 = 0.1U-16-X7S-S2-MU: KAIROSNAME: CC2
2CC3 3CC3 = 0.1U-16-X7S-S2-MU: KAIROSNAME: CC3
2CC4 3CC4 = 0.1U-16-X7S-S2-MU: KAIROSNAME: CC4
2CC5 3CC5 = 0.1U-16-X7S-S2-MU: KAIROSNAME: CC5
2CC6 3CC6 = 0.1U-16-X7S-S2-MU: KAIROSNAME: CC6
2CC7 3CC7 = 0.1U-16-X7S-S2-MU: KAIROSNAME: CC7
2CC8 3CC8 = 0.1U-16-X7S-S2-MU: KAIROSNAME: CC8
2CC9 3CC9 = 0.1U-16-X7S-S2-MU: KAIROSNAME: CC9
2CC12 3CC12 = 0.1U-16-X7S-S2-MU: KAIROSNAME: CC12
2CC70 3CC70 = 0.1U-16-X7S-S2-MU: KAIROSNAME: CC70
2CC71 3CC71 = 0.1U-16-X7S-S2-MU: KAIROSNAME: CC71
2CC73 3CC73 = 0.1U-16-X7S-S2-MU: KAIROSNAME: CC73
2CC84 3CC84 = 0.1U-16-X7S-S2-MU: KAIROSNAME: CC84
2CC85 2CC182 2CC202 2CC220 3CC85 3CC182 3CC202 3CC220 = 0.1U-16-X7S-S2-MU: KAIROSNAME: CC85
2CC86 3CC86 = 0.1U-16-X7S-S2-MU: KAIROSNAME: CC86
2CC87 3CC87 = 0.1U-16-X7S-S2-MU: KAIROSNAME: CC87
2CC88 2CC90-2CC92 3CC88 3CC90-3CC92 = 0.1U-16-X7S-S2-MU: KAIROSNAME: CC88
2CC89 3CC89 = 0.1U-16-X7S-S2-MU: KAIROSNAME: CC89
2CC96 3CC96 = 0.1U-16-X7S-S2-MU: KAIROSNAME: CC96
2CC101 2CC213 3CC101 3CC213 = 0.1U-16-X7S-S2-MU: KAIROSNAME: CC101
2CC103 2CC211 3CC103 3CC211 = 0.1U-16-X7S-S2-MU: KAIROSNAME: CC103
2CC105 2CC212 3CC105 3CC212 = 0.1U-16-X7S-S2-MU: KAIROSNAME: CC105
2CC112 3CC112 = 0.1U-16-X7S-S2-MU: KAIROSNAME: CC112
2CC195 3CC195 = 4.7U-25-X7R-S8-TY
2K96 3K96 = EC2-5NJ: KAIROSNAME: K95A
2SA1 2SA16 2SA17 2SA19 2SA21 2SA25 3SA1 3SA16 3SA17 3SA19 3SA21 3SA25 = SHORT: KAIROSNAME: SA1
2SA2 2SA15 2SA18 2SA20 2SA22 2SA26 3SA2 3SA15 3SA18 3SA20 3SA22 3SA26 = SHORT: KAIROSNAME: SA2
2SA7 3SA7 = SHORT: KAIROSNAME: SA7
2SA8 3SA8 = SHORT: KAIROSNAME: SA8
2SA9 2SA23 3SA9 3SA23 = SHORT: KAIROSNAME: SA9
2SA10 2SA24 3SA10 3SA24 = SHORT: KAIROSNAME: SA10
2TP_DPS1 3TP_DPS1 = TP01: KAIROSNAME: TP_DPS1
2TP_DPS2 3TP_DPS2 = TP01: KAIROSNAME: S1_DPS3
2TP_DPS3 2TP_DPS4 2TP_DPS9 3TP_DPS3 3TP_DPS4 3TP_DPS9 = TP01: KAIROSNAME: S1_DPS4
2TP_DPS5 3TP_DPS5 = TP01: KAIROSNAME: S1_DPS5
2TP_DPS6 3TP_DPS6 = TP01: KAIROSNAME: TP_DPS8
2TP_DPS7 2TP_DPS8 3TP_DPS7 3TP_DPS8 = TP01: KAIROSNAME: TP_DPS2
SITE2 SITE3 = I6K51D-BGA290-9X7
2BDB5 2BDB8 3BDB5 3BDB8 = BD120-1.5A-S4-MU: KAIROSNAME: BDB5
2BDB6 2BDB7 3BDB6 3BDB7 = BD120-1.5A-S4-MU: KAIROSNAME: BDB6
2C302 2C318 2C1088 2C1093 3C302 3C318 3C1088 3C1093 = 10P-50-N-S2-MU: KAIROSNAME: C318
2C309 2C1086 3C309 3C1086 = 10P-50-N-S2-MU: KAIROSNAME: C309
2C310 2C1087 3C310 3C1087 = 10P-50-N-S2-MU: KAIROSNAME: C310
2C320 2C1091 3C320 3C1091 = 10P-50-N-S2-MU: KAIROSNAME: C320
2C922 2C1090 3C922 3C1090 = 0.1U-16-X-S4-MU: KAIROSNAME: C922
2C923 2C1089 3C923 3C1089 = 0.1U-16-X-S4-MU: KAIROSNAME: C923
2C924 3C924 = 10P-50-N-S2-MU: KAIROSNAME: C924
2R168 2R1099 3R168 3R1099 = 42.2-1-S2: KAIROSNAME: R168
2R170 2R1100 3R170 3R1100 = 42.2-1-S2: KAIROSNAME: R170
2R172 2R1104 3R172 3R1104 = 0-5-S2: KAIROSNAME: R172
2R176 2R1089 2R1106 2R1115 3R176 3R1089 3R1106 3R1115 = 42.2-1-S2: KAIROSNAME: R176
2R178 2R1088 2R1103 2R1114 3R178 3R1088 3R1103 3R1114 = 42.2-1-S2: KAIROSNAME: R178
2R180 2R1110 3R180 3R1110 = 42.2-1-S2: KAIROSNAME: R180
2R182 2R1111 3R182 3R1111 = 42.2-1-S2: KAIROSNAME: R182
2R234 2R1117-2R1119 3R234 3R1117-3R1119 = 0-1-S4-YA
2R646 2R1107 3R646 3R1107 = 42.2-1-S2: KAIROSNAME: R646
2R647 2R1109 3R647 3R1109 = 42.2-1-S2: KAIROSNAME: R647
2R659 2R1105 3R659 3R1105 = 10K-1-S2-WA: KAIROSNAME: R659
2R661 2R1101 3R661 3R1101 = 4.7K-1-S2: KAIROSNAME: R661
2R662 2R1102 3R662 3R1102 = 0-5-S2: KAIROSNAME: R662
2R663 2R1098 3R663 3R1098 = 4.7K-1-S2: KAIROSNAME: R663
2R664 3R664 = 42.2-1-S2: KAIROSNAME: R664
2R666 3R666 = 42.2-1-S2: KAIROSNAME: R666
2R672 2R1108 3R672 3R1108 = 10K-1-S2-WA: KAIROSNAME: R672
2U408 2U455 3U408 3U455 = CBTL06GP213EE-TFBGA50: KAIROSNAME: U408
2U409 2U456 3U409 3U456 = CBTL06GP213EE-TFBGA50: KAIROSNAME: U409

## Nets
DGND: 2C302.2 2C309.2 2C310.2 2C318.2 2C320.2 2C922.1 2C923.1 2C924.2 2C1086.2 2C1087.2 2C1088.2 2C1089.1 2C1090.1 2C1091.2 2C1093.2 2CA1.2 2CA2.2 2CA7.2 2CA8.2 2CA19.2 2CA20.2 2CA21.2 2CA22.2 2CA23.2 2CA24.2 2CA25.2 2CA26.2 2CA27.2 2CA34.2 2CA35.2 2CA36.2 2CA37.2 2CA38.2 2CA39.2 2CC1.2 2CC2.2 2CC3.2 2CC4.2 2CC5.2 2CC6.2 2CC7.2 2CC8.2 2CC9.2 2CC12.2 2CC13.2 2CC14.2 2CC15.2 2CC16.2 2CC70.2 2CC71.2 2CC73.2 2CC84.2 2CC85.2 2CC86.2 2CC87.2 2CC88.2 2CC89.2 2CC90.2 2CC91.2 2CC92.2 2CC96.2 2CC101.2 2CC103.2 2CC105.2 2CC112.2 2CC130.2 2CC182.2 2CC195.2 2CC202.2 2CC211.2 2CC212.2 2CC213.2 2CC214.2 2CC215.2 2CC216.2 2CC217.2 2CC218.2 2CC219.2 2CC220.2 2R659.2 2R672.2 2R1105.2 2R1108.2 2SA2.1 2SA7.1 2SA10.1 2SA15.1 2SA18.1 2SA20.1 2SA22.1 2SA24.1 2SA26.1 2U408.B3(GND) 2U408.C8(GND) 2U408.G2(GND) 2U408.G8(GND) 2U408.H4(GND) 2U408.H7(GND) 2U409.B3(GND) 2U409.C8(GND) 2U409.G2(GND) 2U409.G8(GND) 2U409.H4(GND) 2U409.H7(GND) 2U455.B3(GND) 2U455.C8(GND) 2U455.G2(GND) 2U455.G8(GND) 2U455.H4(GND) 2U455.H7(GND) 2U456.B3(GND) 2U456.C8(GND) 2U456.G2(GND) 2U456.G8(GND) 2U456.H4(GND) 2U456.H7(GND) 3C302.2 3C309.2 3C310.2 3C318.2 3C320.2 3C922.1 3C923.1 3C924.2 3C1086.2 3C1087.2 3C1088.2 3C1089.1 3C1090.1 3C1091.2 3C1093.2 3CA1.2 3CA2.2 3CA7.2 3CA8.2 3CA19.2 3CA20.2 3CA21.2 3CA22.2 3CA23.2 3CA24.2 3CA25.2 3CA26.2 3CA27.2 3CA34.2 3CA35.2 3CA36.2 3CA37.2 3CA38.2 3CA39.2 3CC1.2 3CC2.2 3CC3.2 3CC4.2 3CC5.2 3CC6.2 3CC7.2 3CC8.2 3CC9.2 3CC12.2 3CC13.2 3CC14.2 3CC15.2 3CC16.2 3CC70.2 3CC71.2 3CC73.2 3CC84.2 3CC85.2 3CC86.2 3CC87.2 3CC88.2 3CC89.2 3CC90.2 3CC91.2 3CC92.2 3CC96.2 3CC101.2 3CC103.2 3CC105.2 3CC112.2 3CC130.2 3CC182.2 3CC195.2 3CC202.2 3CC211.2 3CC212.2 3CC213.2 3CC214.2 3CC215.2 3CC216.2 3CC217.2 3CC218.2 3CC219.2 3CC220.2 3R659.2 3R672.2 3R1105.2 3R1108.2 3SA2.1 3SA7.1 3SA10.1 3SA15.1 3SA18.1 3SA20.1 3SA22.1 3SA24.1 3SA26.1 3U408.B3(GND) 3U408.C8(GND) 3U408.G2(GND) 3U408.G8(GND) 3U408.H4(GND) 3U408.H7(GND) 3U409.B3(GND) 3U409.C8(GND) 3U409.G2(GND) 3U409.G8(GND) 3U409.H4(GND) 3U409.H7(GND) 3U455.B3(GND) 3U455.C8(GND) 3U455.G2(GND) 3U455.G8(GND) 3U455.H4(GND) 3U455.H7(GND) 3U456.B3(GND) 3U456.C8(GND) 3U456.G2(GND) 3U456.G8(GND) 3U456.H4(GND) 3U456.H7(GND) ; also on sheet 1 2 3 4 5 6 7 8 9 10 17 18 19 20 21 22 23 24 25 26 27 28 30 31 32 33 34 35 36 37
2SA_CBIT_R96: 2K96.12(V-)
2SA_CBIT_S20: 2R662.2 2R1102.2
2SA_CBIT_S29: 2R172.2 2R1104.2
3SA_CBIT_R96: 3K96.12(V-)
3SA_CBIT_S20: 3R662.2 3R1102.2
3SA_CBIT_S29: 3R172.2 3R1104.2
S2_3V3_RX0_MIPI: 2BDB5.2 2C922.2 2R661.2 2U408.A2(VDD) 2U408.J4(VDD)
S2_3V3_RX1_MIPI: 2BDB6.2 2C923.2 2R663.2 2U409.A2(VDD) 2U409.J4(VDD)
S2_3V3_TX0_MIPI: 2BDB8.2 2C1090.2 2R1101.2 2U455.A2(VDD) 2U455.J4(VDD)
S2_3V3_TX1_MIPI: 2BDB7.2 2C1089.2 2R1098.2 2U456.A2(VDD) 2U456.J4(VDD)
S2_B_DCH001: 2CC195.1 SITE2.M18(VDDP18_LDO_P0)
S2_DPS3: 2CA20.1 2CA21.1 2CC84.1 2CC85.1 2CC86.1 2CC87.1 2CC88.1 2CC89.1 2CC90.1 2CC91.1 2CC92.1 2SA17.1 2TP_DPS3.1(TP) SITE2.F4(VDDP18_P1) SITE2.F17(AVDD18_NODIE) SITE2.G5(AVDD18_MIPI_TX) SITE2.H4(AVDD18_USB) SITE2.J18(AVDD18_OTP) SITE2.L5(AVDD18_AUD) SITE2.R11(AVDD18_PLL_DDR) SITE2.R14(VDD1_DRAM[0]) SITE2.R15(VDD1_DRAM[1])
S2_DPS4: 2CA34.1 2CA35.1 2CC182.1 2CC202.1 2SA19.1 2TP_DPS4.1(TP) SITE2.H19(AVDD33_ETH) SITE2.J5(AVDD33_USB)
S2_Mpdch37+: 2U408.B8(DIN2_0+)
S2_Mpdch37-: 2U408.B9(DIN2_0-)
S2_Mpdch38+: 2U455.B8(DIN2_0+)
S2_Mpdch38-: 2U455.B9(DIN2_0-)
S2_Mpdch39+: 2U408.D8(DIN2_1+)
S2_Mpdch39-: 2U408.D9(DIN2_1-)
S2_Mpdch40+: 2U455.D8(DIN2_1+)
S2_Mpdch40-: 2U455.D9(DIN2_1-)
S2_Mpdch41+: 2U408.E8(DIN2_2+)
S2_Mpdch41-: 2U408.E9(DIN2_2-)
S2_Mpdch42+: 2U455.E8(DIN2_2+)
S2_Mpdch42-: 2U455.E9(DIN2_2-)
S2_Mpdch43+: 2U409.B8(DIN2_0+)
S2_Mpdch43-: 2U409.B9(DIN2_0-)
S2_Mpdch44+: 2U456.B8(DIN2_0+)
S2_Mpdch44-: 2U456.B9(DIN2_0-)
S2_Mpdch45+: 2U409.D8(DIN2_1+)
S2_Mpdch45-: 2U409.D9(DIN2_1-)
S2_Mpdch46+: 2U456.D8(DIN2_1+)
S2_Mpdch46-: 2U456.D9(DIN2_1-)
S2_Mpdch47+: 2U409.E8(DIN2_2+)
S2_Mpdch47-: 2U409.E9(DIN2_2-)
S2_MUX_3V3: 2R234.2 2R1117.2 2R1118.2 2R1119.2 ; also on sheet 32
S2_OUT_RX0_CH0_ABC_CASE+: 2U408.B2(DOUT_0+) SITE2.B10(PAD_OUTP_RX0_CH[0])
S2_OUT_RX0_CH0_ABC_CASE-: 2U408.B1(DOUT_0-) SITE2.A10(PAD_OUTN_RX0_CH[0])
S2_OUT_RX0_CH0_B_CASE+: 2R647.1 2U408.B4(DIN1_0+)
S2_OUT_RX0_CH0_B_CASE-: 2R646.1 2U408.A4(DIN1_0-)
S2_OUT_RX0_CH0_C_CASE: 2C309.1 2R646.2 2R647.2
S2_OUT_RX0_CH1_ABC_CASE+: 2U408.D2(DOUT_1+) SITE2.B9(PAD_OUTP_RX0_CH[1])
S2_OUT_RX0_CH1_ABC_CASE-: 2U408.D1(DOUT_1-) SITE2.B8(PAD_OUTN_RX0_CH[1])
S2_OUT_RX0_CH1_B_CASE+: 2R168.1 2U408.B5(DIN1_1+)
S2_OUT_RX0_CH1_B_CASE-: 2R170.1 2U408.A5(DIN1_1-)
S2_OUT_RX0_CH1_C_CASE: 2C310.1 2R168.2 2R170.2
S2_OUT_RX0_CH2_ABC_CASE+: 2U408.E2(DOUT_2+) SITE2.A8(PAD_OUTP_RX0_CH[2])
S2_OUT_RX0_CH2_ABC_CASE-: 2U408.E1(DOUT_2-) SITE2.B7(PAD_OUTN_RX0_CH[2])
S2_OUT_RX0_CH2_B_CASE+: 2R176.1 2U408.B6(DIN1_2+)
S2_OUT_RX0_CH2_B_CASE-: 2R178.1 2U408.A6(DIN1_2-)
S2_OUT_RX0_CH2_C_CASE: 2C318.1 2R176.2 2R178.2
S2_OUT_RX0_CH3_ABC_CASE+: 2U409.B2(DOUT_0+) SITE2.B6(PAD_OUTP_RX0_CH[3])
S2_OUT_RX0_CH3_ABC_CASE-: 2U409.B1(DOUT_0-) SITE2.A6(PAD_OUTN_RX0_CH[3])
S2_OUT_RX0_CH3_B_CASE+: 2R1089.1 2U409.B4(DIN1_0+)
S2_OUT_RX0_CH3_B_CASE-: 2R1088.1 2U409.A4(DIN1_0-)
S2_OUT_RX0_CH3_C_CASE: 2C302.1 2R1088.2 2R1089.2
S2_OUT_RX0_CH4_ABC_CASE+: 2U409.D2(DOUT_1+) SITE2.B5(PAD_OUTP_RX0_CH[4])
S2_OUT_RX0_CH4_ABC_CASE-: 2U409.D1(DOUT_1-) SITE2.B4(PAD_OUTN_RX0_CH[4])
S2_OUT_RX0_CH4_B_CASE+: 2R180.1 2U409.B5(DIN1_1+)
S2_OUT_RX0_CH4_B_CASE-: 2R182.1 2U409.A5(DIN1_1-)
S2_OUT_RX0_CH4_C_CASE: 2C320.1 2R180.2 2R182.2
S2_OUT_RX0_CH5_ABC_CASE+: 2U409.E2(DOUT_2+) SITE2.A4(PAD_OUTP_RX0_CH[5])
S2_OUT_RX0_CH5_ABC_CASE-: 2U409.E1(DOUT_2-) SITE2.B3(PAD_OUTN_RX0_CH[5])
S2_OUT_RX0_CH5_B_CASE+: 2R666.1 2U409.B6(DIN1_2+)
S2_OUT_RX0_CH5_B_CASE-: 2R664.1 2U409.A6(DIN1_2-)
S2_OUT_RX0_CH5_C_CASE: 2C924.1 2R664.2 2R666.2
S2_OUT_TX0_CH0_ABC_CASE+: 2U455.B2(DOUT_0+) SITE2.A2(PAD_OUTP_TX0_CH[0])
S2_OUT_TX0_CH0_ABC_CASE-: 2U455.B1(DOUT_0-) SITE2.B1(PAD_OUTN_TX0_CH[0])
S2_OUT_TX0_CH0_B_CASE+: 2R1109.1 2U455.B4(DIN1_0+)
S2_OUT_TX0_CH0_B_CASE-: 2R1107.1 2U455.A4(DIN1_0-)
S2_OUT_TX0_CH0_C_CASE: 2C1086.1 2R1107.2 2R1109.2
S2_OUT_TX0_CH1_ABC_CASE+: 2U455.D2(DOUT_1+) SITE2.C1(PAD_OUTP_TX0_CH[1])
S2_OUT_TX0_CH1_ABC_CASE-: 2U455.D1(DOUT_1-) SITE2.C2(PAD_OUTN_TX0_CH[1])
S2_OUT_TX0_CH1_B_CASE+: 2R1099.1 2U455.B5(DIN1_1+)
S2_OUT_TX0_CH1_B_CASE-: 2R1100.1 2U455.A5(DIN1_1-)
S2_OUT_TX0_CH1_C_CASE: 2C1087.1 2R1099.2 2R1100.2
S2_OUT_TX0_CH2_ABC_CASE+: 2U455.E2(DOUT_2+) SITE2.D2(PAD_OUTP_TX0_CH[2])
S2_OUT_TX0_CH2_ABC_CASE-: 2U455.E1(DOUT_2-) SITE2.E1(PAD_OUTN_TX0_CH[2])
S2_OUT_TX0_CH2_B_CASE+: 2R1106.1 2U455.B6(DIN1_2+)
S2_OUT_TX0_CH2_B_CASE-: 2R1103.1 2U455.A6(DIN1_2-)
S2_OUT_TX0_CH2_C_CASE: 2C1088.1 2R1103.2 2R1106.2
S2_OUT_TX0_CH3_ABC_CASE+: 2U456.B2(DOUT_0+) SITE2.E2(PAD_OUTP_TX0_CH[3])
S2_OUT_TX0_CH3_ABC_CASE-: 2U456.B1(DOUT_0-) SITE2.F2(PAD_OUTN_TX0_CH[3])
S2_OUT_TX0_CH3_B_CASE+: 2R1115.1 2U456.B4(DIN1_0+)
S2_OUT_TX0_CH3_B_CASE-: 2R1114.1 2U456.A4(DIN1_0-)
S2_OUT_TX0_CH3_C_CASE: 2C1093.1 2R1114.2 2R1115.2
S2_OUT_TX0_CH4_ABC_CASE+: 2U456.D2(DOUT_1+) SITE2.G1(PAD_OUTP_TX0_CH[4])
S2_OUT_TX0_CH4_ABC_CASE-: 2U456.D1(DOUT_1-) SITE2.G2(PAD_OUTN_TX0_CH[4])
S2_OUT_TX0_CH4_B_CASE+: 2R1110.1 2U456.B5(DIN1_1+)
S2_OUT_TX0_CH4_B_CASE-: 2R1111.1 2U456.A5(DIN1_1-)
S2_OUT_TX0_CH4_C_CASE: 2C1091.1 2R1110.2 2R1111.2
S2_PWR_F001: 2CA26.1 2CA27.1 2CC112.1 2SA16.1 2TP_DPS2.1(TP) SITE2.F15(DVDD_NODIE)
S2_PWR_F004: 2CA22.1 2CA23.1 2CC96.1 2SA21.1 2TP_DPS5.1(TP) SITE2.E10(AVDD33_RTC)
S2_PWR_F005: 2CA7.1 2CA8.1 2CC70.1 2CC71.1 2CC73.1 2SA8.1 2TP_DPS6.1(TP) SITE2.G18(VDDP3318_PM) SITE2.N17(VDDP3318_P0) SITE2.P3(VDDP3318_P2)
S2_PWR_F006: 2CA24.1 2CA25.1 2CC101.1 2CC103.1 2CC105.1 2SA9.1 2TP_DPS7.1(TP) SITE2.T13(VDD2_DRAM[0]) SITE2.T14(VDD2_DRAM[1]) SITE2.U13(VDD2_DRAM[2])
S2_PWR_F007: 2CA36.1 2CA37.1 2CC211.1 2CC212.1 2CC213.1 2SA23.1 2TP_DPS8.1(TP) SITE2.T10(VDDQ_DRAM[0]) SITE2.T11(VDDQ_DRAM[1]) SITE2.U11(VDDQ_DRAM[2])
S2_PWR_F008: 2CA38.1 2CA39.1 2CC220.1 2SA25.1 2TP_DPS9.1(TP) SITE2.K19(AVDD18_XTAL)
S2_PWR_GS001: 2SA15.2
S2_PWR_GS002: 2SA18.2
S2_PWR_GS003: 2SA20.2
S2_PWR_GS004: 2SA22.2
S2_PWR_GS005: 2SA7.2
S2_PWR_GS006: 2SA10.2
S2_PWR_GS007: 2SA24.2
S2_PWR_GS008: 2SA26.2
S2_PWR_M_F001: 2CA1.1 2CA2.1 2CC1.1 2CC2.1 2CC3.1 2CC4.1 2CC5.1 2CC6.1 2CC7.1 2CC8.1 2CC9.1 2CC12.1 2CC13.1 2CC14.1 2CC15.1 2CC16.1 2CC130.1 2CC214.1 2CC215.1 2CC216.1 2CC217.1 2CC218.1 2CC219.1 2K96.4 2K96.9 2SA1.1 2TP_DPS1.1(TP) SITE2.F6(AVDDL_MIPI_RX) SITE2.F7(VDD_CPU[0]) SITE2.F8(VDD_CPU[1]) SITE2.G6(AVDDL_MIPI_TX) SITE2.G7(VDD_CPU[2]) SITE2.G8(VDD_CPU[3]) SITE2.G10(VDD[0]) SITE2.G11(VDD[1]) SITE2.H7(VDD_CPU[4]) SITE2.H8(VDD_CPU[5]) SITE2.H10(VDD[2]) SITE2.H11(VDD[3]) SITE2.H12(VDD[4]) SITE2.J10(VDD[5]) SITE2.J11(VDD[6]) SITE2.J12(VDD[7]) SITE2.J13(VDD[8]) SITE2.K10(VDD[9]) SITE2.K11(VDD[10]) SITE2.K12(VDD[11]) SITE2.K13(VDD[12])
S2_PWR_M_GS001: 2SA2.2
S2_PWR_M_S001: 2SA1.2
S2_PWR_S001: 2SA16.2
S2_PWR_S002: 2SA17.2
S2_PWR_S003: 2SA19.2
S2_PWR_S004: 2SA21.2
S2_PWR_S005: 2SA8.2
S2_PWR_S006: 2SA9.2
S2_PWR_S007: 2SA23.2
S2_PWR_S008: 2SA25.2
S3_3V3_RX0_MIPI: 3BDB5.2 3C922.2 3R661.2 3U408.A2(VDD) 3U408.J4(VDD)
S3_3V3_RX1_MIPI: 3BDB6.2 3C923.2 3R663.2 3U409.A2(VDD) 3U409.J4(VDD)
S3_3V3_TX0_MIPI: 3BDB8.2 3C1090.2 3R1101.2 3U455.A2(VDD) 3U455.J4(VDD)
S3_3V3_TX1_MIPI: 3BDB7.2 3C1089.2 3R1098.2 3U456.A2(VDD) 3U456.J4(VDD)
S3_B_DCH001: 3CC195.1 SITE3.M18(VDDP18_LDO_P0)
S3_DPS3: 3CA20.1 3CA21.1 3CC84.1 3CC85.1 3CC86.1 3CC87.1 3CC88.1 3CC89.1 3CC90.1 3CC91.1 3CC92.1 3SA17.1 3TP_DPS3.1(TP) SITE3.F4(VDDP18_P1) SITE3.F17(AVDD18_NODIE) SITE3.G5(AVDD18_MIPI_TX) SITE3.H4(AVDD18_USB) SITE3.J18(AVDD18_OTP) SITE3.L5(AVDD18_AUD) SITE3.R11(AVDD18_PLL_DDR) SITE3.R14(VDD1_DRAM[0]) SITE3.R15(VDD1_DRAM[1])
S3_DPS4: 3CA34.1 3CA35.1 3CC182.1 3CC202.1 3SA19.1 3TP_DPS4.1(TP) SITE3.H19(AVDD33_ETH) SITE3.J5(AVDD33_USB)
S3_Mpdch37+: 3U408.B8(DIN2_0+)
S3_Mpdch37-: 3U408.B9(DIN2_0-)
S3_Mpdch38+: 3U455.B8(DIN2_0+)
S3_Mpdch38-: 3U455.B9(DIN2_0-)
S3_Mpdch39+: 3U408.D8(DIN2_1+)
S3_Mpdch39-: 3U408.D9(DIN2_1-)
S3_Mpdch40+: 3U455.D8(DIN2_1+)
S3_Mpdch40-: 3U455.D9(DIN2_1-)
S3_Mpdch41+: 3U408.E8(DIN2_2+)
S3_Mpdch41-: 3U408.E9(DIN2_2-)
S3_Mpdch42+: 3U455.E8(DIN2_2+)
S3_Mpdch42-: 3U455.E9(DIN2_2-)
S3_Mpdch43+: 3U409.B8(DIN2_0+)
S3_Mpdch43-: 3U409.B9(DIN2_0-)
S3_Mpdch44+: 3U456.B8(DIN2_0+)
S3_Mpdch44-: 3U456.B9(DIN2_0-)
S3_Mpdch45+: 3U409.D8(DIN2_1+)
S3_Mpdch45-: 3U409.D9(DIN2_1-)
S3_Mpdch46+: 3U456.D8(DIN2_1+)
S3_Mpdch46-: 3U456.D9(DIN2_1-)
S3_Mpdch47+: 3U409.E8(DIN2_2+)
S3_Mpdch47-: 3U409.E9(DIN2_2-)
S3_MUX_3V3: 3R234.2 3R1117.2 3R1118.2 3R1119.2 ; also on sheet 30
S3_OUT_RX0_CH0_ABC_CASE+: 3U408.B2(DOUT_0+) SITE3.B10(PAD_OUTP_RX0_CH[0])
S3_OUT_RX0_CH0_ABC_CASE-: 3U408.B1(DOUT_0-) SITE3.A10(PAD_OUTN_RX0_CH[0])
S3_OUT_RX0_CH0_B_CASE+: 3R647.1 3U408.B4(DIN1_0+)
S3_OUT_RX0_CH0_B_CASE-: 3R646.1 3U408.A4(DIN1_0-)
S3_OUT_RX0_CH0_C_CASE: 3C309.1 3R646.2 3R647.2
S3_OUT_RX0_CH1_ABC_CASE+: 3U408.D2(DOUT_1+) SITE3.B9(PAD_OUTP_RX0_CH[1])
S3_OUT_RX0_CH1_ABC_CASE-: 3U408.D1(DOUT_1-) SITE3.B8(PAD_OUTN_RX0_CH[1])
S3_OUT_RX0_CH1_B_CASE+: 3R168.1 3U408.B5(DIN1_1+)
S3_OUT_RX0_CH1_B_CASE-: 3R170.1 3U408.A5(DIN1_1-)
S3_OUT_RX0_CH1_C_CASE: 3C310.1 3R168.2 3R170.2
S3_OUT_RX0_CH2_ABC_CASE+: 3U408.E2(DOUT_2+) SITE3.A8(PAD_OUTP_RX0_CH[2])
S3_OUT_RX0_CH2_ABC_CASE-: 3U408.E1(DOUT_2-) SITE3.B7(PAD_OUTN_RX0_CH[2])
S3_OUT_RX0_CH2_B_CASE+: 3R176.1 3U408.B6(DIN1_2+)
S3_OUT_RX0_CH2_B_CASE-: 3R178.1 3U408.A6(DIN1_2-)
S3_OUT_RX0_CH2_C_CASE: 3C318.1 3R176.2 3R178.2
S3_OUT_RX0_CH3_ABC_CASE+: 3U409.B2(DOUT_0+) SITE3.B6(PAD_OUTP_RX0_CH[3])
S3_OUT_RX0_CH3_ABC_CASE-: 3U409.B1(DOUT_0-) SITE3.A6(PAD_OUTN_RX0_CH[3])
S3_OUT_RX0_CH3_B_CASE+: 3R1089.1 3U409.B4(DIN1_0+)
S3_OUT_RX0_CH3_B_CASE-: 3R1088.1 3U409.A4(DIN1_0-)
S3_OUT_RX0_CH3_C_CASE: 3C302.1 3R1088.2 3R1089.2
S3_OUT_RX0_CH4_ABC_CASE+: 3U409.D2(DOUT_1+) SITE3.B5(PAD_OUTP_RX0_CH[4])
S3_OUT_RX0_CH4_ABC_CASE-: 3U409.D1(DOUT_1-) SITE3.B4(PAD_OUTN_RX0_CH[4])
S3_OUT_RX0_CH4_B_CASE+: 3R180.1 3U409.B5(DIN1_1+)
S3_OUT_RX0_CH4_B_CASE-: 3R182.1 3U409.A5(DIN1_1-)
S3_OUT_RX0_CH4_C_CASE: 3C320.1 3R180.2 3R182.2
S3_OUT_RX0_CH5_ABC_CASE+: 3U409.E2(DOUT_2+) SITE3.A4(PAD_OUTP_RX0_CH[5])
S3_OUT_RX0_CH5_ABC_CASE-: 3U409.E1(DOUT_2-) SITE3.B3(PAD_OUTN_RX0_CH[5])
S3_OUT_RX0_CH5_B_CASE+: 3R666.1 3U409.B6(DIN1_2+)
S3_OUT_RX0_CH5_B_CASE-: 3R664.1 3U409.A6(DIN1_2-)
S3_OUT_RX0_CH5_C_CASE: 3C924.1 3R664.2 3R666.2
S3_OUT_TX0_CH0_ABC_CASE+: 3U455.B2(DOUT_0+) SITE3.A2(PAD_OUTP_TX0_CH[0])
S3_OUT_TX0_CH0_ABC_CASE-: 3U455.B1(DOUT_0-) SITE3.B1(PAD_OUTN_TX0_CH[0])
S3_OUT_TX0_CH0_B_CASE+: 3R1109.1 3U455.B4(DIN1_0+)
S3_OUT_TX0_CH0_B_CASE-: 3R1107.1 3U455.A4(DIN1_0-)
S3_OUT_TX0_CH0_C_CASE: 3C1086.1 3R1107.2 3R1109.2
S3_OUT_TX0_CH1_ABC_CASE+: 3U455.D2(DOUT_1+) SITE3.C1(PAD_OUTP_TX0_CH[1])
S3_OUT_TX0_CH1_ABC_CASE-: 3U455.D1(DOUT_1-) SITE3.C2(PAD_OUTN_TX0_CH[1])
S3_OUT_TX0_CH1_B_CASE+: 3R1099.1 3U455.B5(DIN1_1+)
S3_OUT_TX0_CH1_B_CASE-: 3R1100.1 3U455.A5(DIN1_1-)
S3_OUT_TX0_CH1_C_CASE: 3C1087.1 3R1099.2 3R1100.2
S3_OUT_TX0_CH2_ABC_CASE+: 3U455.E2(DOUT_2+) SITE3.D2(PAD_OUTP_TX0_CH[2])
S3_OUT_TX0_CH2_ABC_CASE-: 3U455.E1(DOUT_2-) SITE3.E1(PAD_OUTN_TX0_CH[2])
S3_OUT_TX0_CH2_B_CASE+: 3R1106.1 3U455.B6(DIN1_2+)
S3_OUT_TX0_CH2_B_CASE-: 3R1103.1 3U455.A6(DIN1_2-)
S3_OUT_TX0_CH2_C_CASE: 3C1088.1 3R1103.2 3R1106.2
S3_OUT_TX0_CH3_ABC_CASE+: 3U456.B2(DOUT_0+) SITE3.E2(PAD_OUTP_TX0_CH[3])
S3_OUT_TX0_CH3_ABC_CASE-: 3U456.B1(DOUT_0-) SITE3.F2(PAD_OUTN_TX0_CH[3])
S3_OUT_TX0_CH3_B_CASE+: 3R1115.1 3U456.B4(DIN1_0+)
S3_OUT_TX0_CH3_B_CASE-: 3R1114.1 3U456.A4(DIN1_0-)
S3_OUT_TX0_CH3_C_CASE: 3C1093.1 3R1114.2 3R1115.2
S3_OUT_TX0_CH4_ABC_CASE+: 3U456.D2(DOUT_1+) SITE3.G1(PAD_OUTP_TX0_CH[4])
S3_OUT_TX0_CH4_ABC_CASE-: 3U456.D1(DOUT_1-) SITE3.G2(PAD_OUTN_TX0_CH[4])
S3_OUT_TX0_CH4_B_CASE+: 3R1110.1 3U456.B5(DIN1_1+)
S3_OUT_TX0_CH4_B_CASE-: 3R1111.1 3U456.A5(DIN1_1-)
S3_OUT_TX0_CH4_C_CASE: 3C1091.1 3R1110.2 3R1111.2
S3_PWR_F001: 3CA26.1 3CA27.1 3CC112.1 3SA16.1 3TP_DPS2.1(TP) SITE3.F15(DVDD_NODIE)
S3_PWR_F004: 3CA22.1 3CA23.1 3CC96.1 3SA21.1 3TP_DPS5.1(TP) SITE3.E10(AVDD33_RTC)
S3_PWR_F005: 3CA7.1 3CA8.1 3CC70.1 3CC71.1 3CC73.1 3SA8.1 3TP_DPS6.1(TP) SITE3.G18(VDDP3318_PM) SITE3.N17(VDDP3318_P0) SITE3.P3(VDDP3318_P2)
S3_PWR_F006: 3CA24.1 3CA25.1 3CC101.1 3CC103.1 3CC105.1 3SA9.1 3TP_DPS7.1(TP) SITE3.T13(VDD2_DRAM[0]) SITE3.T14(VDD2_DRAM[1]) SITE3.U13(VDD2_DRAM[2])
S3_PWR_F007: 3CA36.1 3CA37.1 3CC211.1 3CC212.1 3CC213.1 3SA23.1 3TP_DPS8.1(TP) SITE3.T10(VDDQ_DRAM[0]) SITE3.T11(VDDQ_DRAM[1]) SITE3.U11(VDDQ_DRAM[2])
S3_PWR_F008: 3CA38.1 3CA39.1 3CC220.1 3SA25.1 3TP_DPS9.1(TP) SITE3.K19(AVDD18_XTAL)
S3_PWR_GS001: 3SA15.2
S3_PWR_GS002: 3SA18.2
S3_PWR_GS003: 3SA20.2
S3_PWR_GS004: 3SA22.2
S3_PWR_GS005: 3SA7.2
S3_PWR_GS006: 3SA10.2
S3_PWR_GS007: 3SA24.2
S3_PWR_GS008: 3SA26.2
S3_PWR_M_F001: 3CA1.1 3CA2.1 3CC1.1 3CC2.1 3CC3.1 3CC4.1 3CC5.1 3CC6.1 3CC7.1 3CC8.1 3CC9.1 3CC12.1 3CC13.1 3CC14.1 3CC15.1 3CC16.1 3CC130.1 3CC214.1 3CC215.1 3CC216.1 3CC217.1 3CC218.1 3CC219.1 3K96.4 3K96.9 3SA1.1 3TP_DPS1.1(TP) SITE3.F6(AVDDL_MIPI_RX) SITE3.F7(VDD_CPU[0]) SITE3.F8(VDD_CPU[1]) SITE3.G6(AVDDL_MIPI_TX) SITE3.G7(VDD_CPU[2]) SITE3.G8(VDD_CPU[3]) SITE3.G10(VDD[0]) SITE3.G11(VDD[1]) SITE3.H7(VDD_CPU[4]) SITE3.H8(VDD_CPU[5]) SITE3.H10(VDD[2]) SITE3.H11(VDD[3]) SITE3.H12(VDD[4]) SITE3.J10(VDD[5]) SITE3.J11(VDD[6]) SITE3.J12(VDD[7]) SITE3.J13(VDD[8]) SITE3.K10(VDD[9]) SITE3.K11(VDD[10]) SITE3.K12(VDD[11]) SITE3.K13(VDD[12])
S3_PWR_M_GS001: 3SA2.2
S3_PWR_M_S001: 3SA1.2
S3_PWR_S001: 3SA16.2
S3_PWR_S002: 3SA17.2
S3_PWR_S003: 3SA19.2
S3_PWR_S004: 3SA21.2
S3_PWR_S005: 3SA8.2
S3_PWR_S006: 3SA9.2
S3_PWR_S007: 3SA23.2
S3_PWR_S008: 3SA25.2
UT1_UP5V: 2K96.1(V+) 3K96.1(V+) ; also on sheet 2 4 6 8 10 17 19 20 21 22 23 24 25 26 27 28 30 31 32 33 34 35 36 37
N22556394: 2CA19.1 2K96.5 2K96.8
N22562598: 2R172.1 2U408.A1(GPU_SEL)
N22562601: 2R661.1 2U408.B7(/XSD)
N22562605: 2R662.1 2U409.A1(GPU_SEL)
N22562608: 2R663.1 2U409.B7(/XSD)
N22562632: 2R672.1 2U409.C2(DDC_AUX_SEL)
N22562670: 2R659.1 2U408.C2(DDC_AUX_SEL)
N22562778: 2R1104.1 2U455.A1(GPU_SEL)
N22562781: 2R1101.1 2U455.B7(/XSD)
N22562785: 2R1102.1 2U456.A1(GPU_SEL)
N22562788: 2R1098.1 2U456.B7(/XSD)
N22562812: 2R1108.1 2U456.C2(DDC_AUX_SEL)
N22562850: 2R1105.1 2U455.C2(DDC_AUX_SEL)
N22562958: 2BDB5.1 2R234.1
N22562960: 2BDB6.1 2R1117.1
N22562962: 2BDB8.1 2R1118.1
N22562964: 2BDB7.1 2R1119.1
N22564315: 3CA19.1 3K96.5 3K96.8
N22570460: 3R172.1 3U408.A1(GPU_SEL)
N22570463: 3R661.1 3U408.B7(/XSD)
N22570467: 3R662.1 3U409.A1(GPU_SEL)
N22570470: 3R663.1 3U409.B7(/XSD)
N22570494: 3R672.1 3U409.C2(DDC_AUX_SEL)
N22570532: 3R659.1 3U408.C2(DDC_AUX_SEL)
N22570640: 3R1104.1 3U455.A1(GPU_SEL)
N22570643: 3R1101.1 3U455.B7(/XSD)
N22570647: 3R1102.1 3U456.A1(GPU_SEL)
N22570650: 3R1098.1 3U456.B7(/XSD)
N22570674: 3R1108.1 3U456.C2(DDC_AUX_SEL)
N22570712: 3R1105.1 3U455.C2(DDC_AUX_SEL)
N22570820: 3BDB5.1 3R234.1
N22570822: 3BDB6.1 3R1117.1
N22570824: 3BDB8.1 3R1118.1
N22570826: 3BDB7.1 3R1119.1

Not connected (* = marked no-connect by the designer): 2K96 3* 10*; 2U408 A8(DIN1_3+)* A9(DIN1_3-)* F1(DOUT_3-)* F2(DOUT_3+)* F8(DIN2_3+)* F9(DIN2_3-)* H1(AUX-)* H2(AUX+)* H3(HPD_2)* H5(DDC_CLK2)* H6(DAUX2+)* H8(DDC_CLK1)* H9(DAUX1+)* J1(HPDIN)* J2(HPD_1)* J3(DDC_CLK)* J5(DDC_DAT2)* J6(DAUX2-)* J7(DDC_DAT)* J8(DDC_DAT1)* J9(DAUX1-)*; 2U409 A8(DIN1_3+)* A9(DIN1_3-)* F1(DOUT_3-)* F2(DOUT_3+)* F8(DIN2_3+)* F9(DIN2_3-)* H1(AUX-)* H2(AUX+)* H3(HPD_2)* H5(DDC_CLK2)* H6(DAUX2+)* H8(DDC_CLK1)* H9(DAUX1+)* J1(HPDIN)* J2(HPD_1)* J3(DDC_CLK)* J5(DDC_DAT2)* J6(DAUX2-)* J7(DDC_DAT)* J8(DDC_DAT1)* J9(DAUX1-)*; 2U455 A8(DIN1_3+)* A9(DIN1_3-)* F1(DOUT_3-)* F2(DOUT_3+)* F8(DIN2_3+)* F9(DIN2_3-)* H1(AUX-)* H2(AUX+)* H3(HPD_2)* H5(DDC_CLK2)* H6(DAUX2+)* H8(DDC_CLK1)* H9(DAUX1+)* J1(HPDIN)* J2(HPD_1)* J3(DDC_CLK)* J5(DDC_DAT2)* J6(DAUX2-)* J7(DDC_DAT)* J8(DDC_DAT1)* J9(DAUX1-)*; 2U456 A6(DIN1_2-)* A8(DIN1_3+)* A9(DIN1_3-)* B6(DIN1_2+)* E1(DOUT_2-)* E2(DOUT_2+)* E8(DIN2_2+)* E9(DIN2_2-)* F1(DOUT_3-)* F2(DOUT_3+)* F8(DIN2_3+)* F9(DIN2_3-)* H1(AUX-)* H2(AUX+)* H3(HPD_2)* H5(DDC_CLK2)* H6(DAUX2+)* H8(DDC_CLK1)* H9(DAUX1+)* J1(HPDIN)* J2(HPD_1)* J3(DDC_CLK)* J5(DDC_DAT2)* J6(DAUX2-)* J7(DDC_DAT)* J8(DDC_DAT1)* J9(DAUX1-)*; 3K96 3* 10*; 3U408 A8(DIN1_3+)* A9(DIN1_3-)* F1(DOUT_3-)* F2(DOUT_3+)* F8(DIN2_3+)* F9(DIN2_3-)* H1(AUX-)* H2(AUX+)* H3(HPD_2)* H5(DDC_CLK2)* H6(DAUX2+)* H8(DDC_CLK1)* H9(DAUX1+)* J1(HPDIN)* J2(HPD_1)* J3(DDC_CLK)* J5(DDC_DAT2)* J6(DAUX2-)* J7(DDC_DAT)* J8(DDC_DAT1)* J9(DAUX1-)*; 3U409 A8(DIN1_3+)* A9(DIN1_3-)* F1(DOUT_3-)* F2(DOUT_3+)* F8(DIN2_3+)* F9(DIN2_3-)* H1(AUX-)* H2(AUX+)* H3(HPD_2)* H5(DDC_CLK2)* H6(DAUX2+)* H8(DDC_CLK1)* H9(DAUX1+)* J1(HPDIN)* J2(HPD_1)* J3(DDC_CLK)* J5(DDC_DAT2)* J6(DAUX2-)* J7(DDC_DAT)* J8(DDC_DAT1)* J9(DAUX1-)*; 3U455 A8(DIN1_3+)* A9(DIN1_3-)* F1(DOUT_3-)* F2(DOUT_3+)* F8(DIN2_3+)* F9(DIN2_3-)* H1(AUX-)* H2(AUX+)* H3(HPD_2)* H5(DDC_CLK2)* H6(DAUX2+)* H8(DDC_CLK1)* H9(DAUX1+)* J1(HPDIN)* J2(HPD_1)* J3(DDC_CLK)* J5(DDC_DAT2)* J6(DAUX2-)* J7(DDC_DAT)* J8(DDC_DAT1)* J9(DAUX1-)*; 3U456 A6(DIN1_2-)* A8(DIN1_3+)* A9(DIN1_3-)* B6(DIN1_2+)* E1(DOUT_2-)* E2(DOUT_2+)* E8(DIN2_2+)* E9(DIN2_2-)* F1(DOUT_3-)* F2(DOUT_3+)* F8(DIN2_3+)* F9(DIN2_3-)* H1(AUX-)* H2(AUX+)* H3(HPD_2)* H5(DDC_CLK2)* H6(DAUX2+)* H8(DDC_CLK1)* H9(DAUX1+)* J1(HPDIN)* J2(HPD_1)* J3(DDC_CLK)* J5(DDC_DAT2)* J6(DAUX2-)* J7(DDC_DAT)* J8(DDC_DAT1)* J9(DAUX1-)*

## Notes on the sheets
sheet 11
- 100 ohm DIFF
- 2023.10.30
- 100 ohm DIFF
- 2023.10.30
sheet 12
- 1.53A/0.7V/0.8V
- 0.05A/0.7V/0.8V
- 0.7A/1.8V
- 0.01A/3.3V
- 200uA/3.3V
- 0.75A/3.3V/1.8V
- 0.1A/1.1V
- 0.03A/0.8V
- 0.02A/1.8V
- Trace Width: 20 mil
sheet 13
- 100 ohm DIFF
- 2023.10.30
- 100 ohm DIFF
- 2023.10.30
sheet 14
- 1.53A/0.7V/0.8V
- 0.05A/0.7V/0.8V
- 0.7A/1.8V
- 0.01A/3.3V
- 200uA/3.3V
- 0.75A/3.3V/1.8V
- 0.1A/1.1V
- 0.03A/0.8V
- 0.02A/1.8V
- Trace Width: 20 mil
sheet 15
- V93K FULL SIZE
- TOP VIEW
- DPS7
- UTILITY8
- DPS8
- MS-DPS
- UTILITY4
- DPS2
- MS-DPS
- UTILITY3
- DPS6
- UTILITY7
- D424
- D420
- D432
- MCB S/M2
- D428
- D316
- D312
- D416
- PS1600(8)
- D412
- PS1600(8)
- D224
- PS1600(7)
- D220
- PS1600(7)
- D232
- MCB S/M2
- D228
- D116
- PS1600(2)
- D112
- PS1600(2)
- D216
- PS1600(6)
- D212
- PS1600(6)
- D423
- D419
- D431
- MCB S/M1
- D427
- D315
- D311
- D415
- PS1600(8)
- D411
- PS1600(8)
- D223
- PS1600(7)
- D219
- PS1600(7)
- D231
- MCB S/M1
- D227
- D115
- PS1600(2)
- D111
- PS1600(2)
- D215
- PS1600(6)
- D211
- PS1600(6)
- D422
- D418
- D430
- DPS64
- D426
- DPS64
- D314
- DPS64
- D310
- DPS64
- D414
- PS1600(8)
- D410
- PS1600(8)
- D222
- PS1600(7)
- D218
- PS1600(7)
- D230
- D226
- D114
- PS1600(2)
- D110
- PS1600(2)
- D214
- PS1600(6)
- D210
- PS1600(6)
- D421
- D417
- D429
- D425
- D313
- D309
- D413
- PS1600(8)
- D409
- PS1600(8)
- D221
- PS1600(7)
- D217
- PS1600(7)
- D229
- D225
- D113
- PS1600(2)
- D109
- PS1600(2)
- D213
- PS1600(6)
- D209
- PS1600(6)
- GROUP 7
- GROUP 8
- GROUP 2
- GROUP 6
- 40mm
- 40mm
- 40mm
- Pin1
- SITE1
- Pin1
- SITE2
- Pin1
- SITE3
- Pin1
- SITE4
- SSI6K51D
- SSI6K51D
- SSI6K51D
- SSI6K51D
- BGA293
- BGA293
- BGA293
- BGA293
- 60mm
- Pin1
- SITE5
- Pin1
- SITE6
- Pin1
- SITE7
- Pin1
- SITE8
- SSI6K51D
- SSI6K51D
- SSI6K51D
- SSI6K51D
- BGA293
- BGA293
- BGA293
- BGA293
- GROUP 4
- GROUP 3
- GROUP 1
- GROUP 5
- D125
- PS1600(4)
- D129
- PS1600(4)
- D117
- PS1600(3)
- D121
- PS1600(3)
- D101
- PS1600(1)
- D105
- PS1600(1)
- D201
- PS1600(5)
- D205
- PS1600(5)
- D325
- D329
- D317
- D321
- D301
- D305
- D401
- D405
- D126
- PS1600(4)
- D130
- PS1600(4)
- D118
- PS1600(3)
- D122
- PS1600(3)
- D102
- PS1600(1)
- D106
- PS1600(1)
- D202
- PS1600(5)
- D206
- PS1600(5)
- D326
- D330
- D318
- D322
- D302
- D306
- D402
- D406
- D127
- PS1600(4)
- D131
- PS1600(4)
- D119
- PS1600(3)
- D123
- PS1600(3)
- D103
- PS1600(1)
- D107
- PS1600(1)
- D203
- PS1600(5)
- D207
- PS1600(5)
- D327
- D331
- D319
- DPS64
- D323
- DPS64
- D303
- DPS64
- D307
- DPS64
- D403
- D407
- D128
- PS1600(4)
- D132
- PS1600(4)
- D120
- PS1600(3)
- D124
- PS1600(3)
- D104
- PS1600(1)
- D108
- PS1600(1)
- D204
- PS1600(5)
- D208
- PS1600(5)
- D328
- D332
- D320
- D324
- D304
- D308
- D404
- D408
- UTILITY5
- DPS1
- UTILITY1
- DPS3
- MS-DPS
- UTILITY2
- DPS1
- MS-DPS
- UTILITY6
- DPS1
- Operating temperature : -40¢XC ~130¢XC
sheet 16
- HISTORY, Ver.: A1
- 2026/10/27
- Initial
- 2026/10/28
- Update V0.1
